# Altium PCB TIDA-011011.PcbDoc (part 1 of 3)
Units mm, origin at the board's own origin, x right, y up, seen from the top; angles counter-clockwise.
Board outline 61 x 47.5 mm, 4 copper layers (Top Layer, Layer 1, Layer 2, Bottom Layer), stack 1.787 mm thick; 171 components, 73 nets, 455 pads, 298 vias.
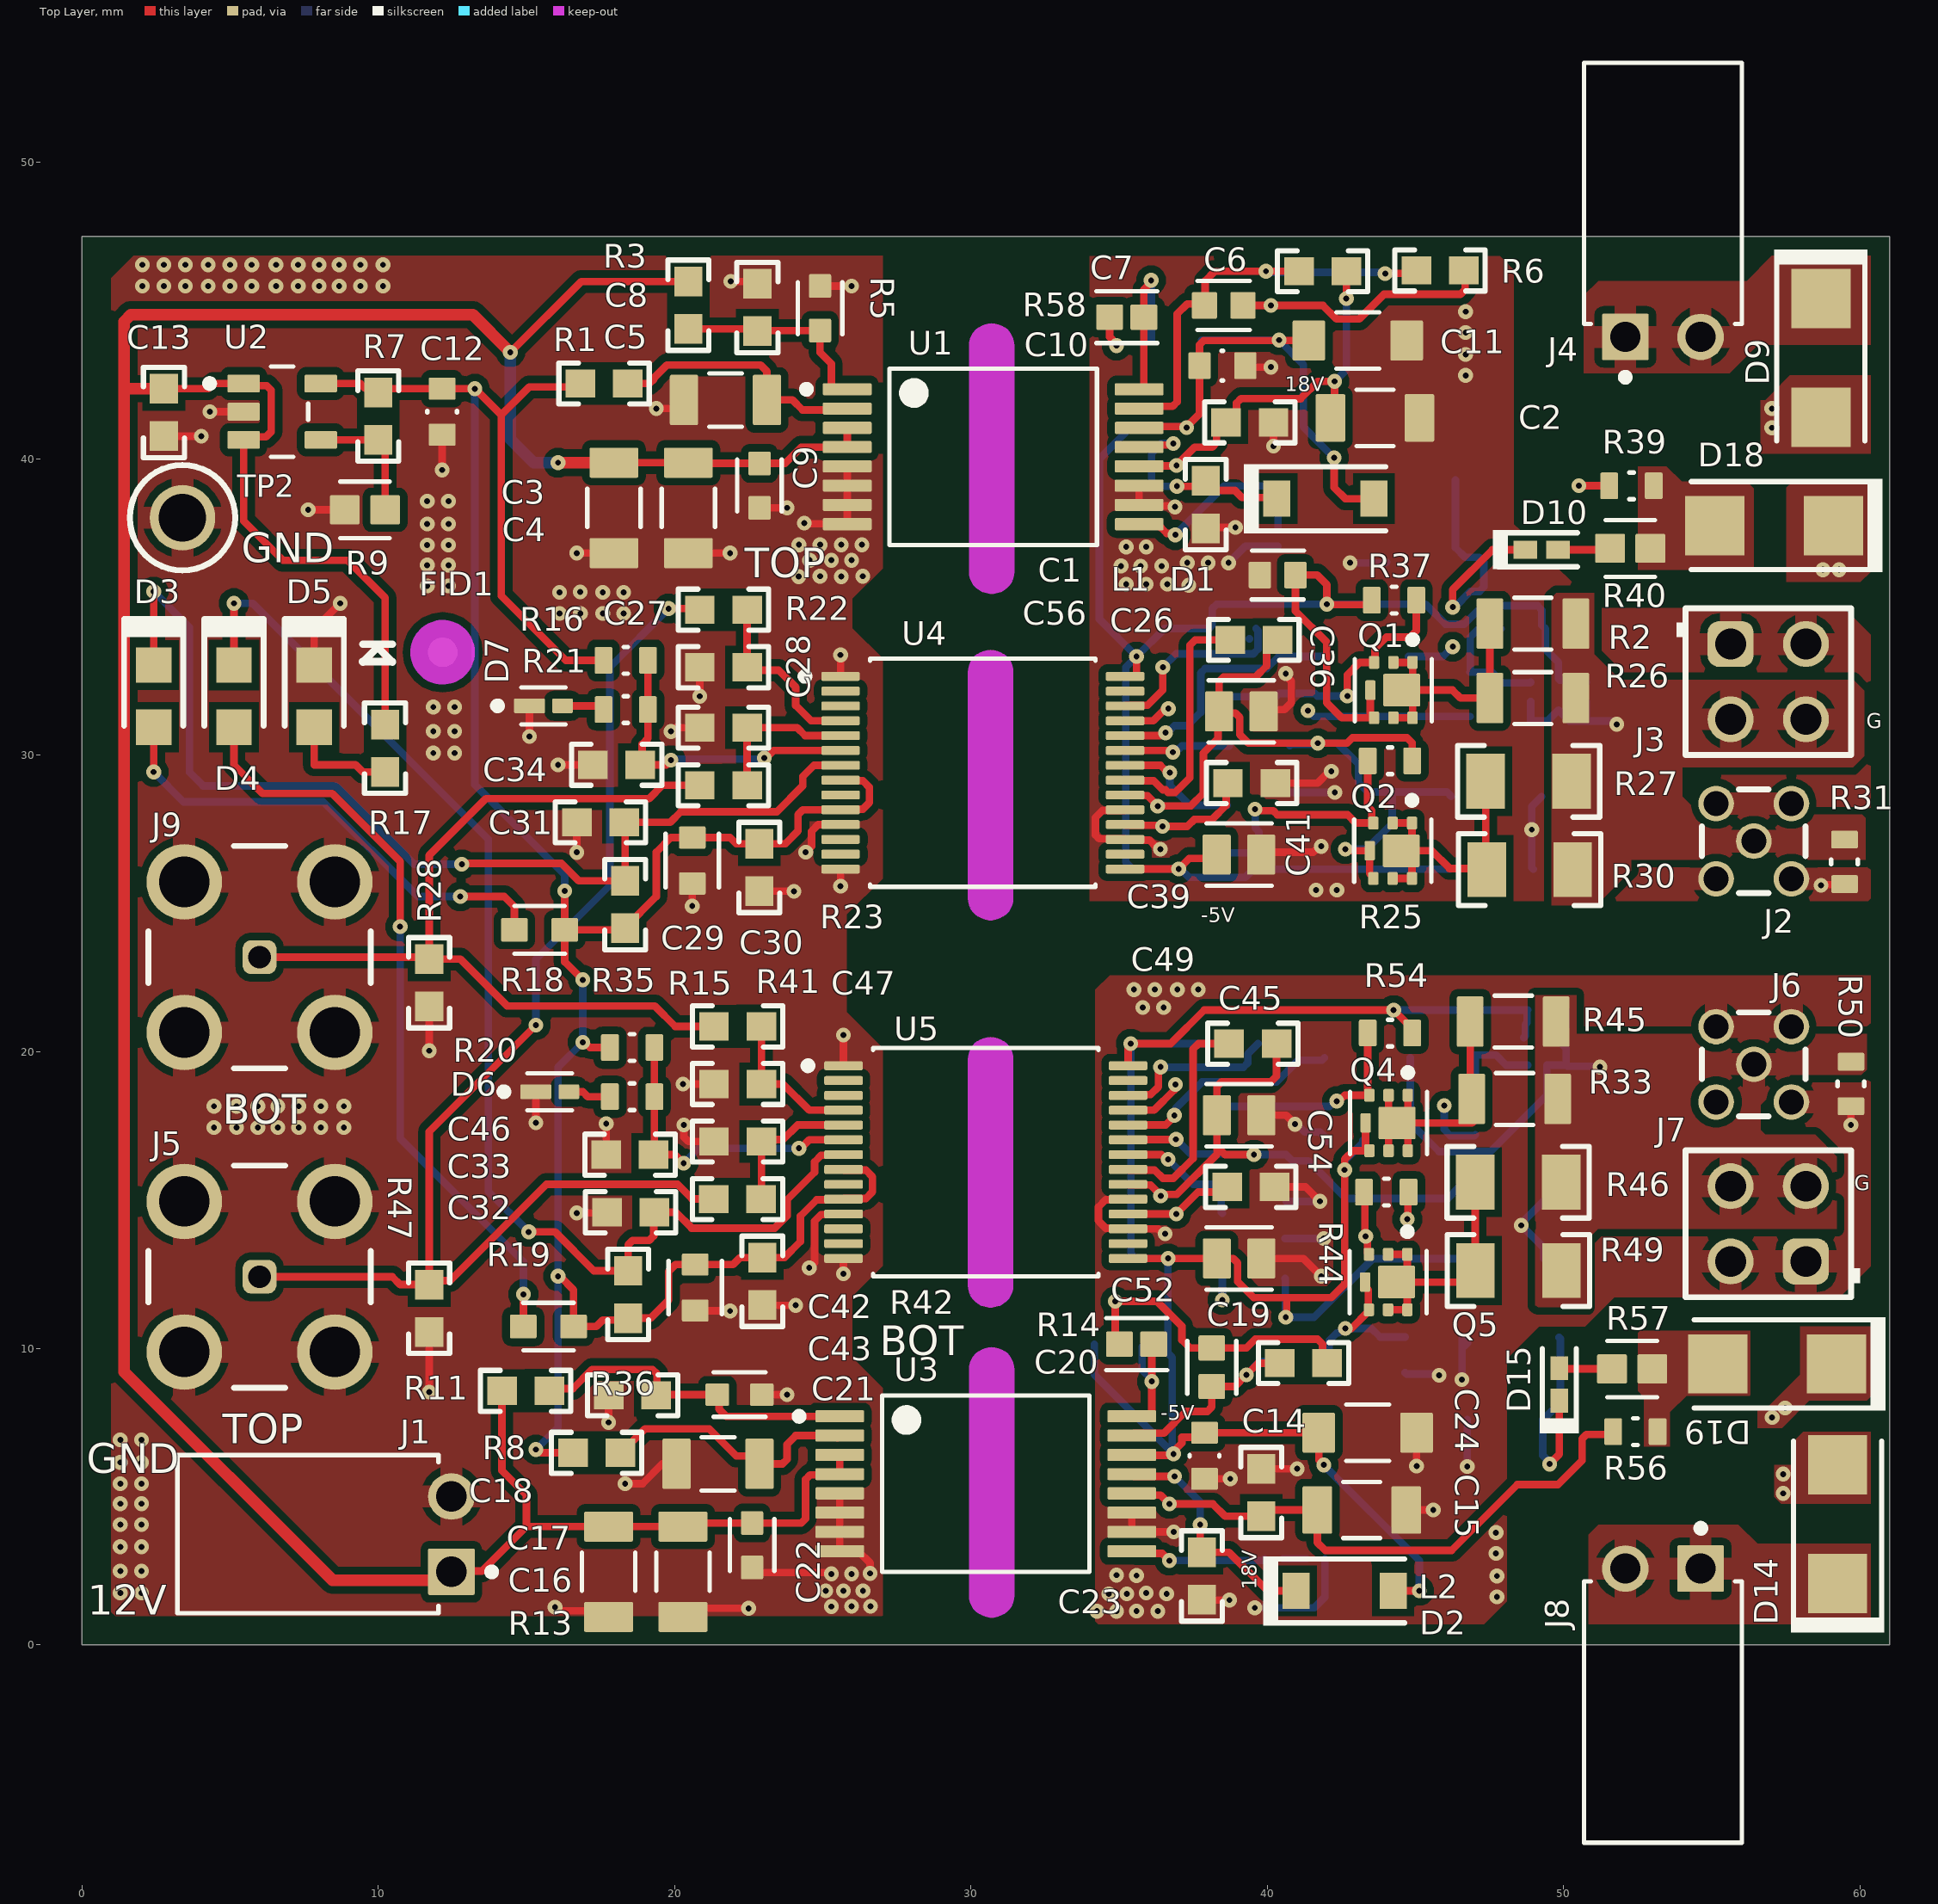
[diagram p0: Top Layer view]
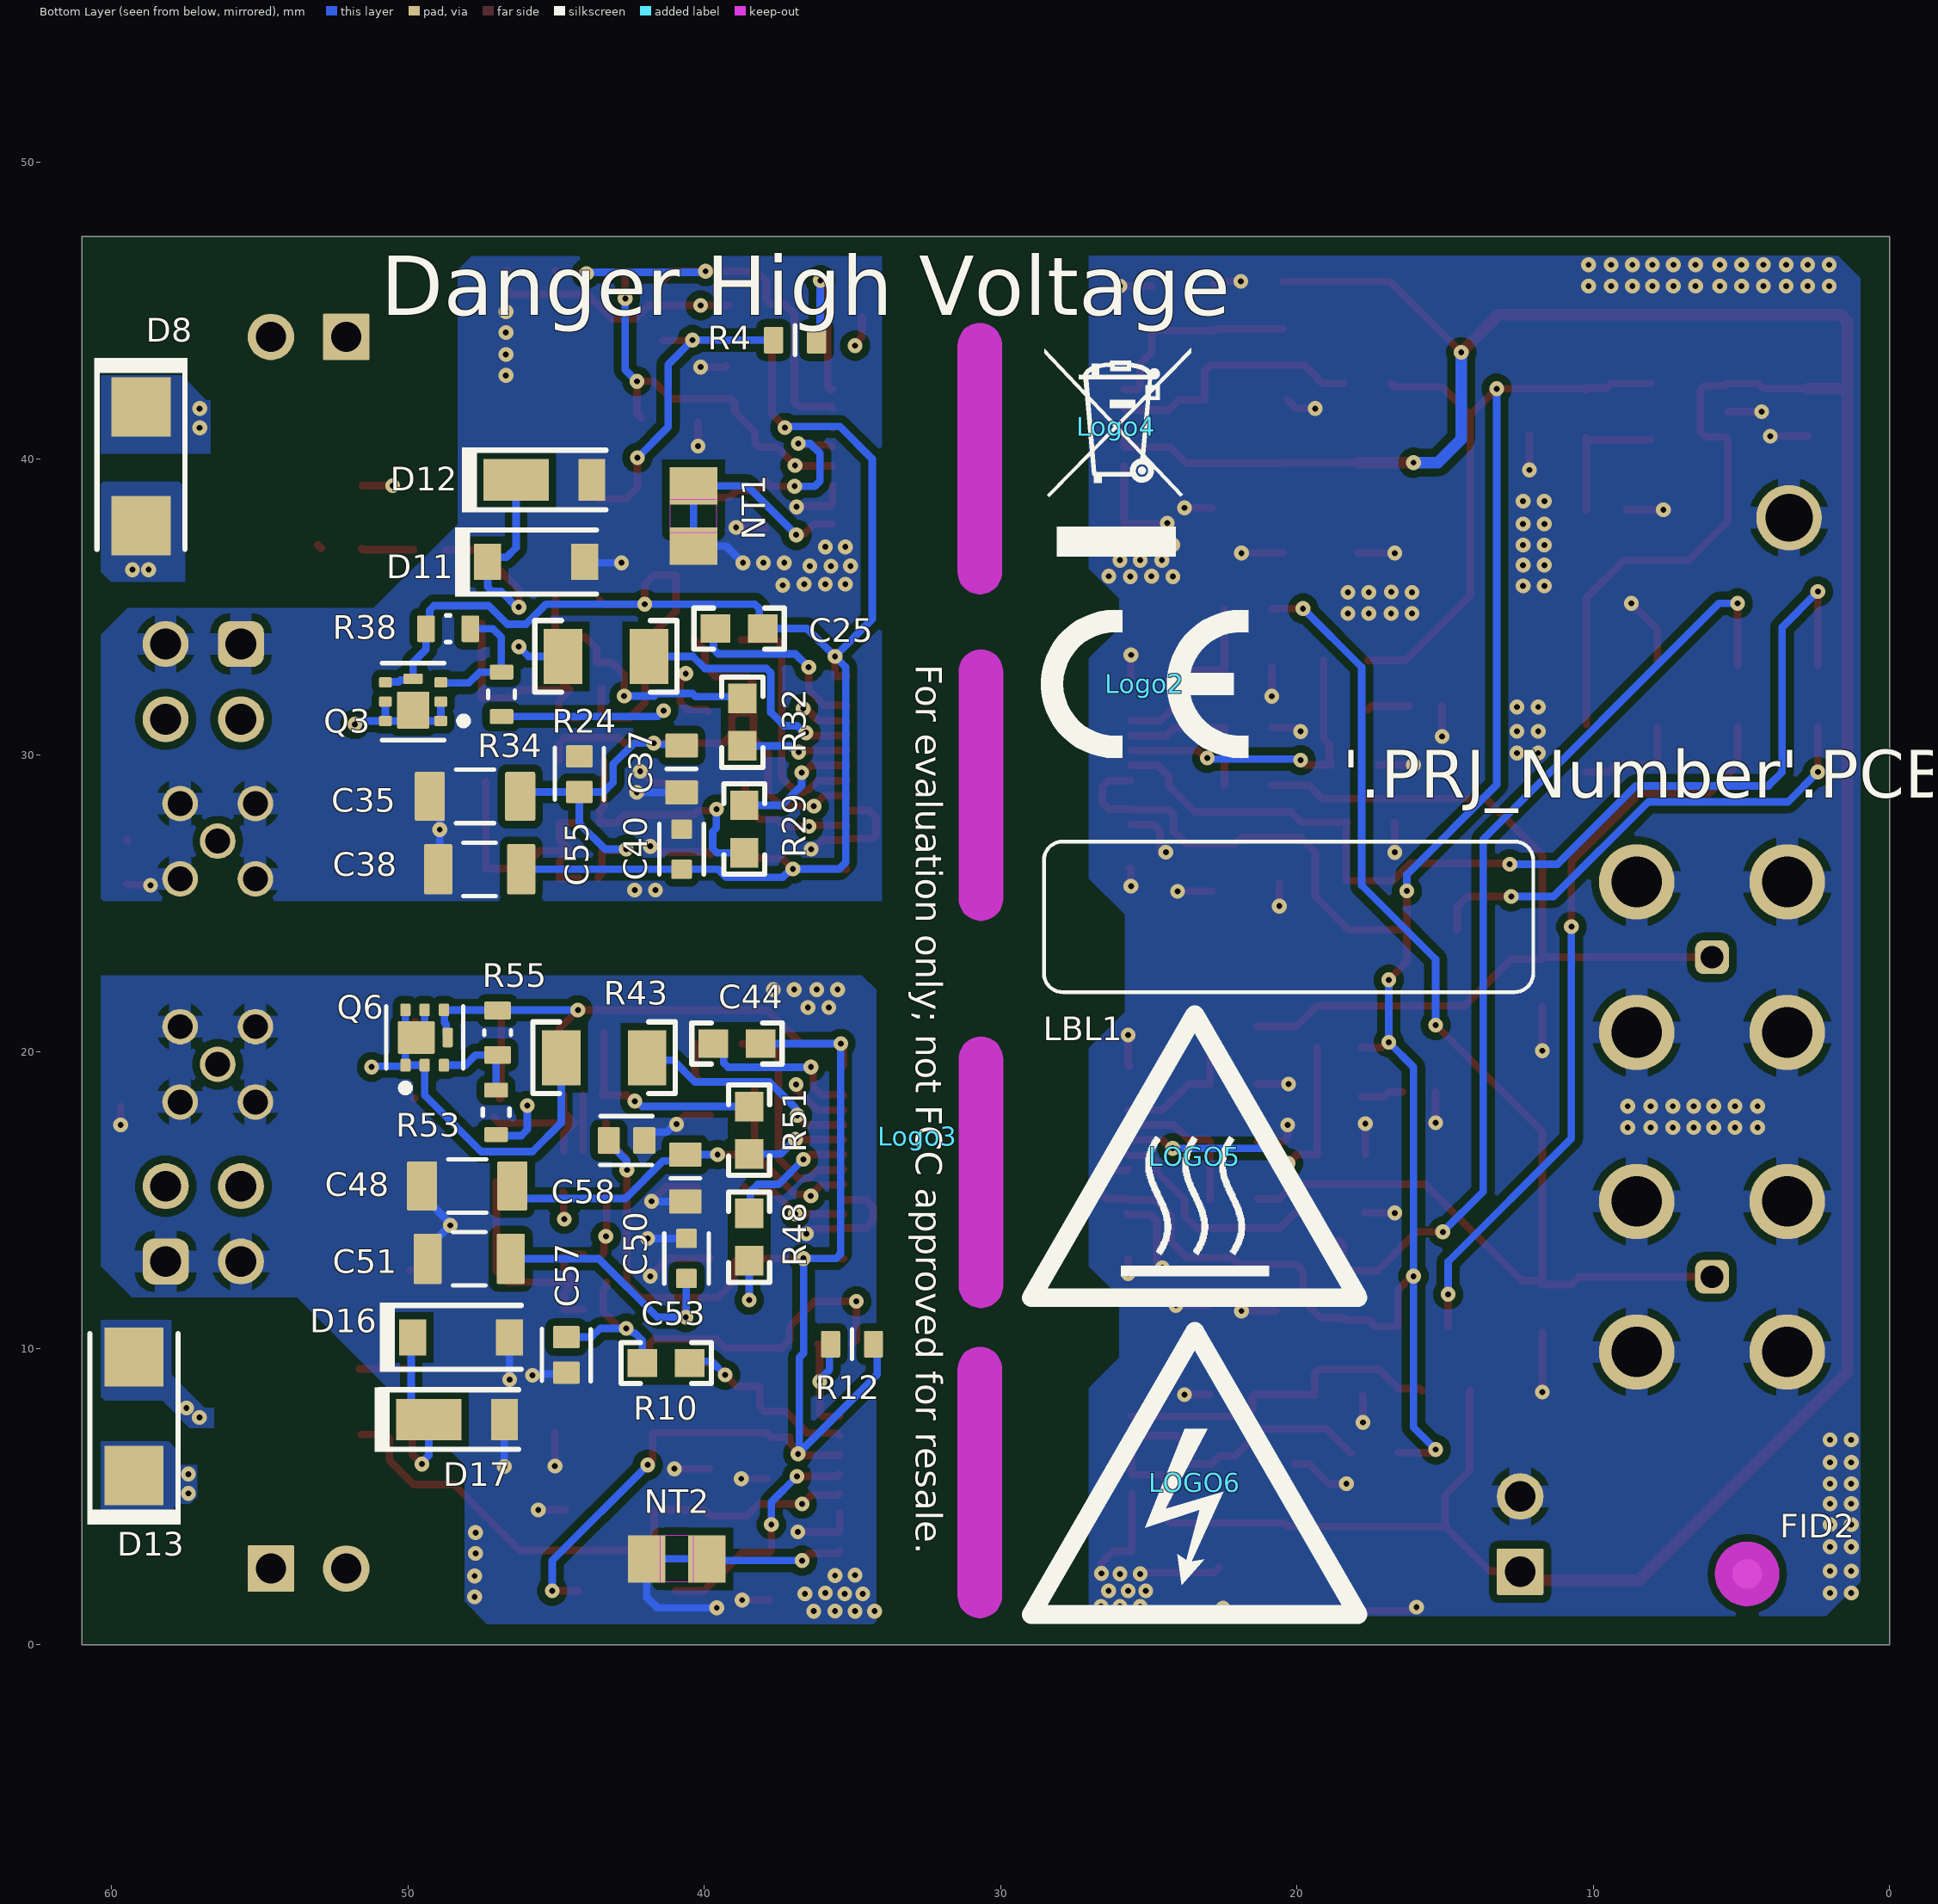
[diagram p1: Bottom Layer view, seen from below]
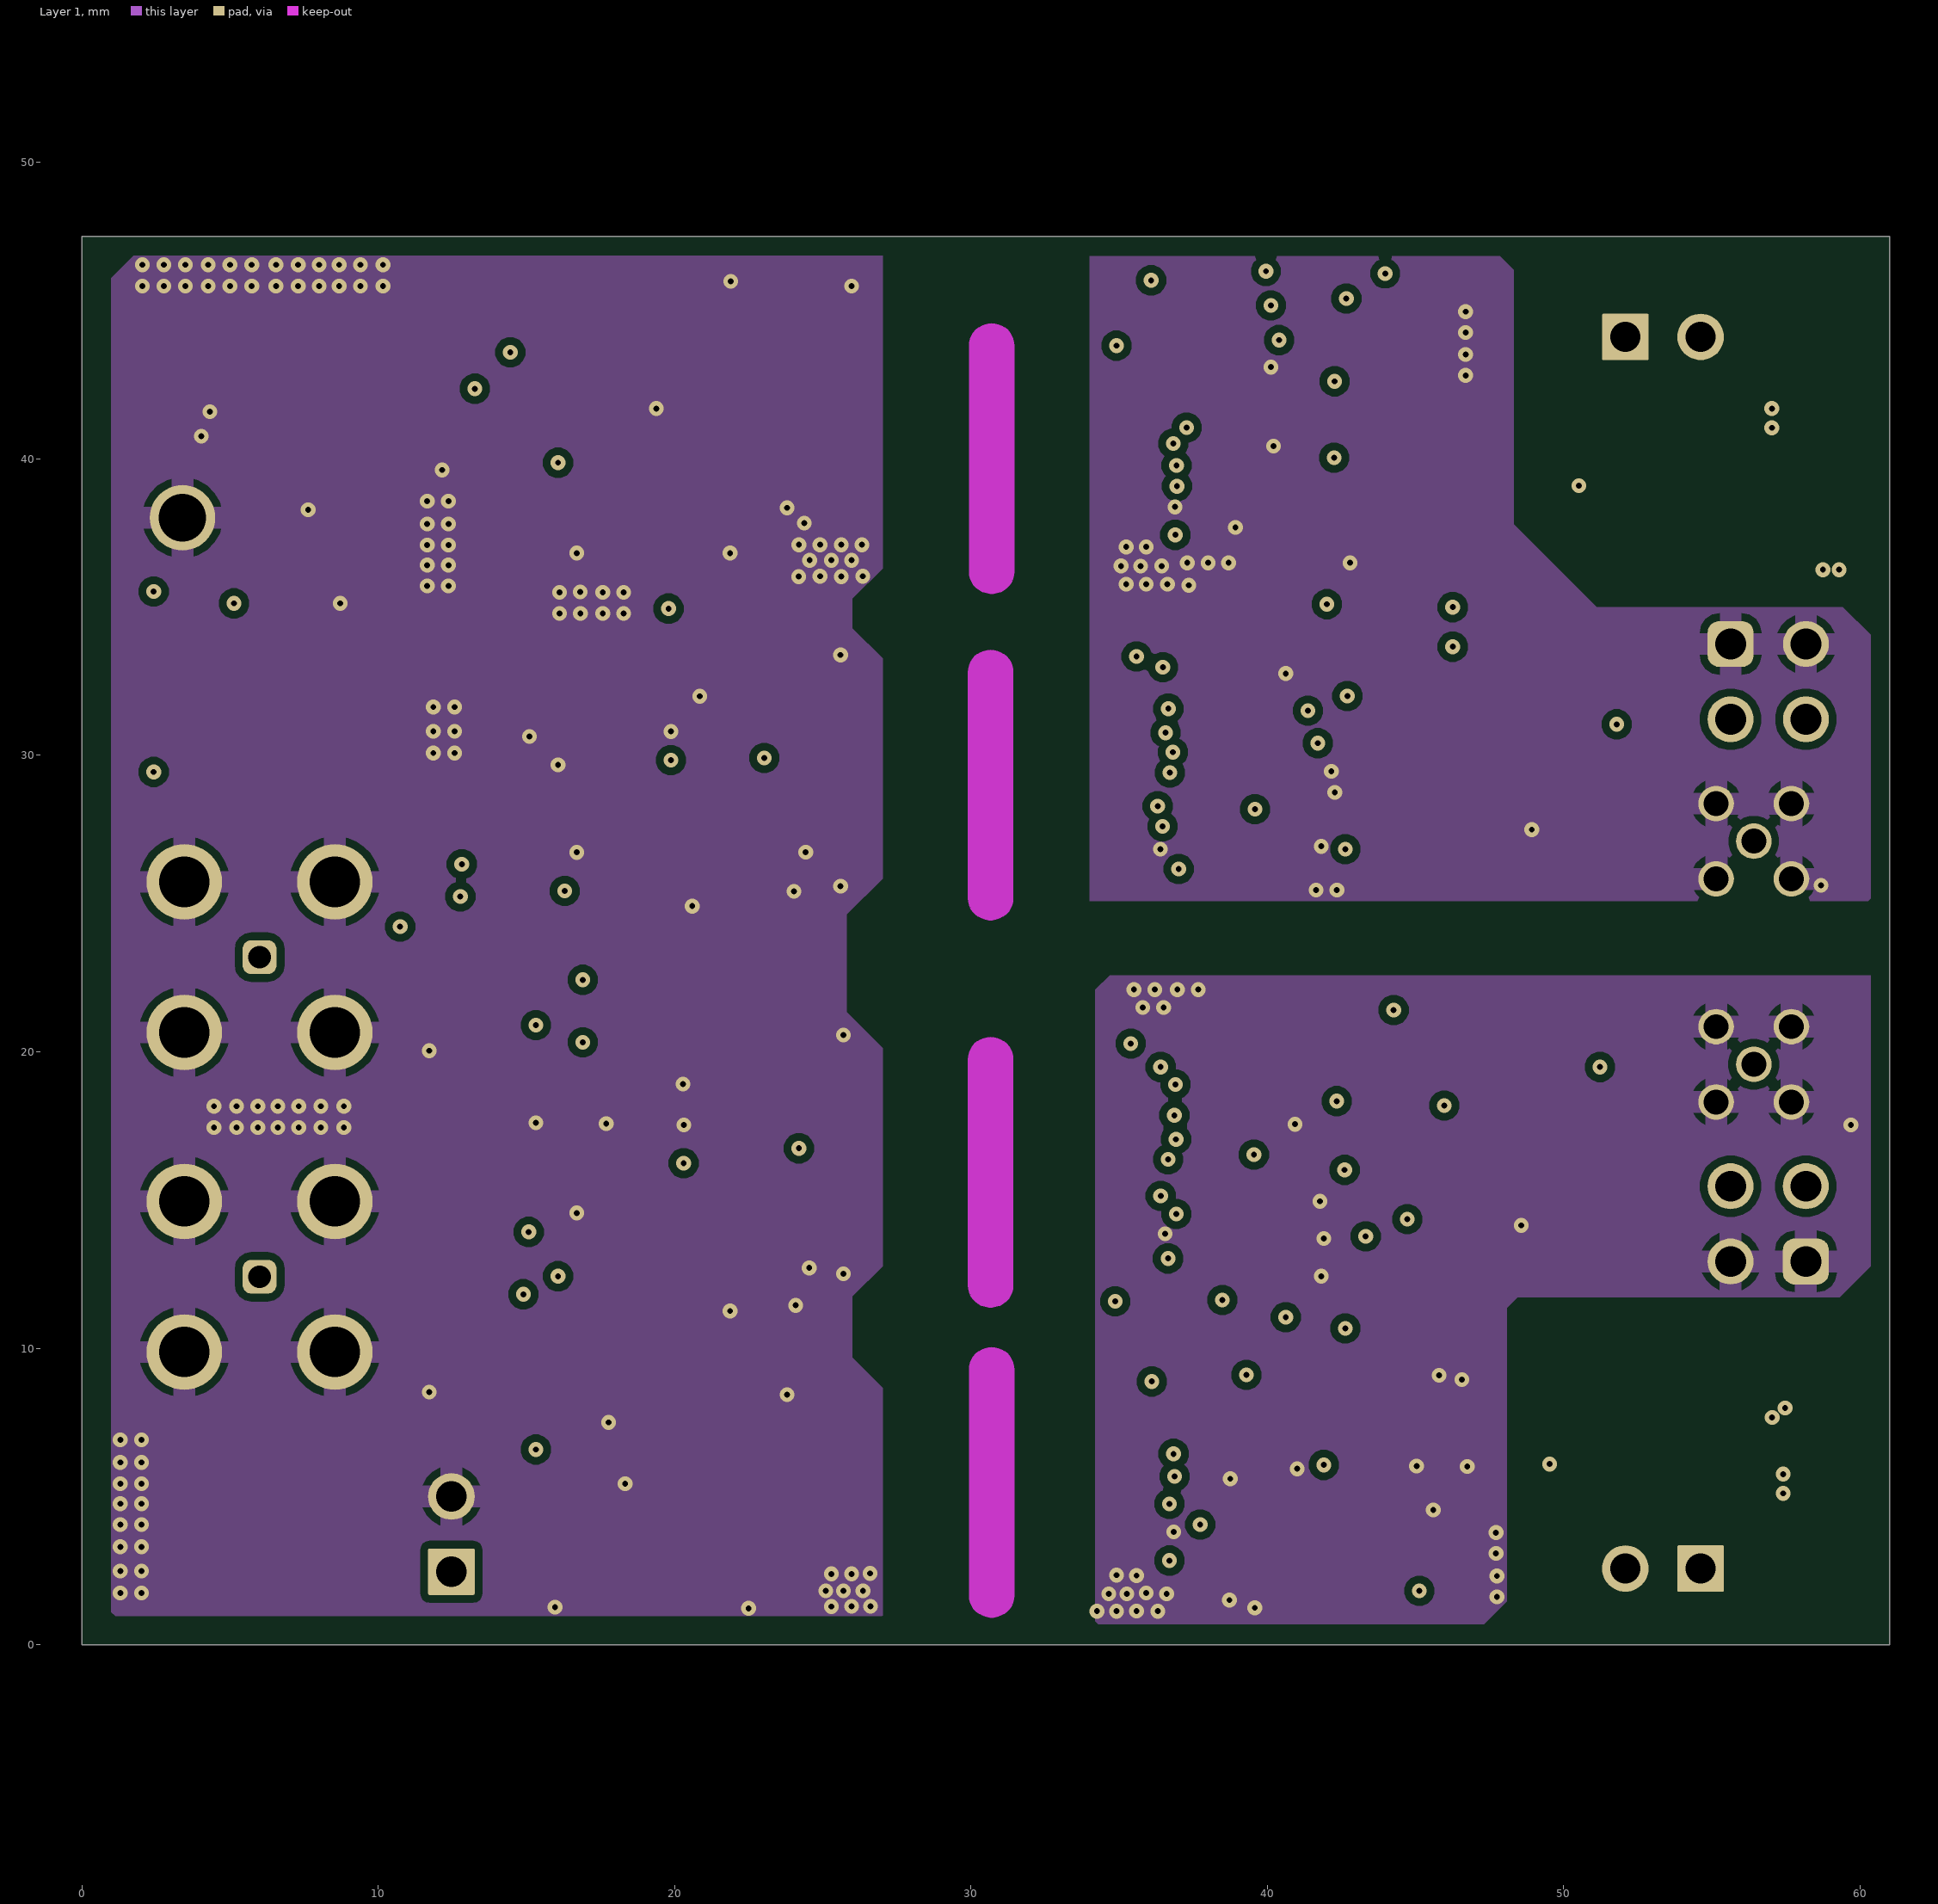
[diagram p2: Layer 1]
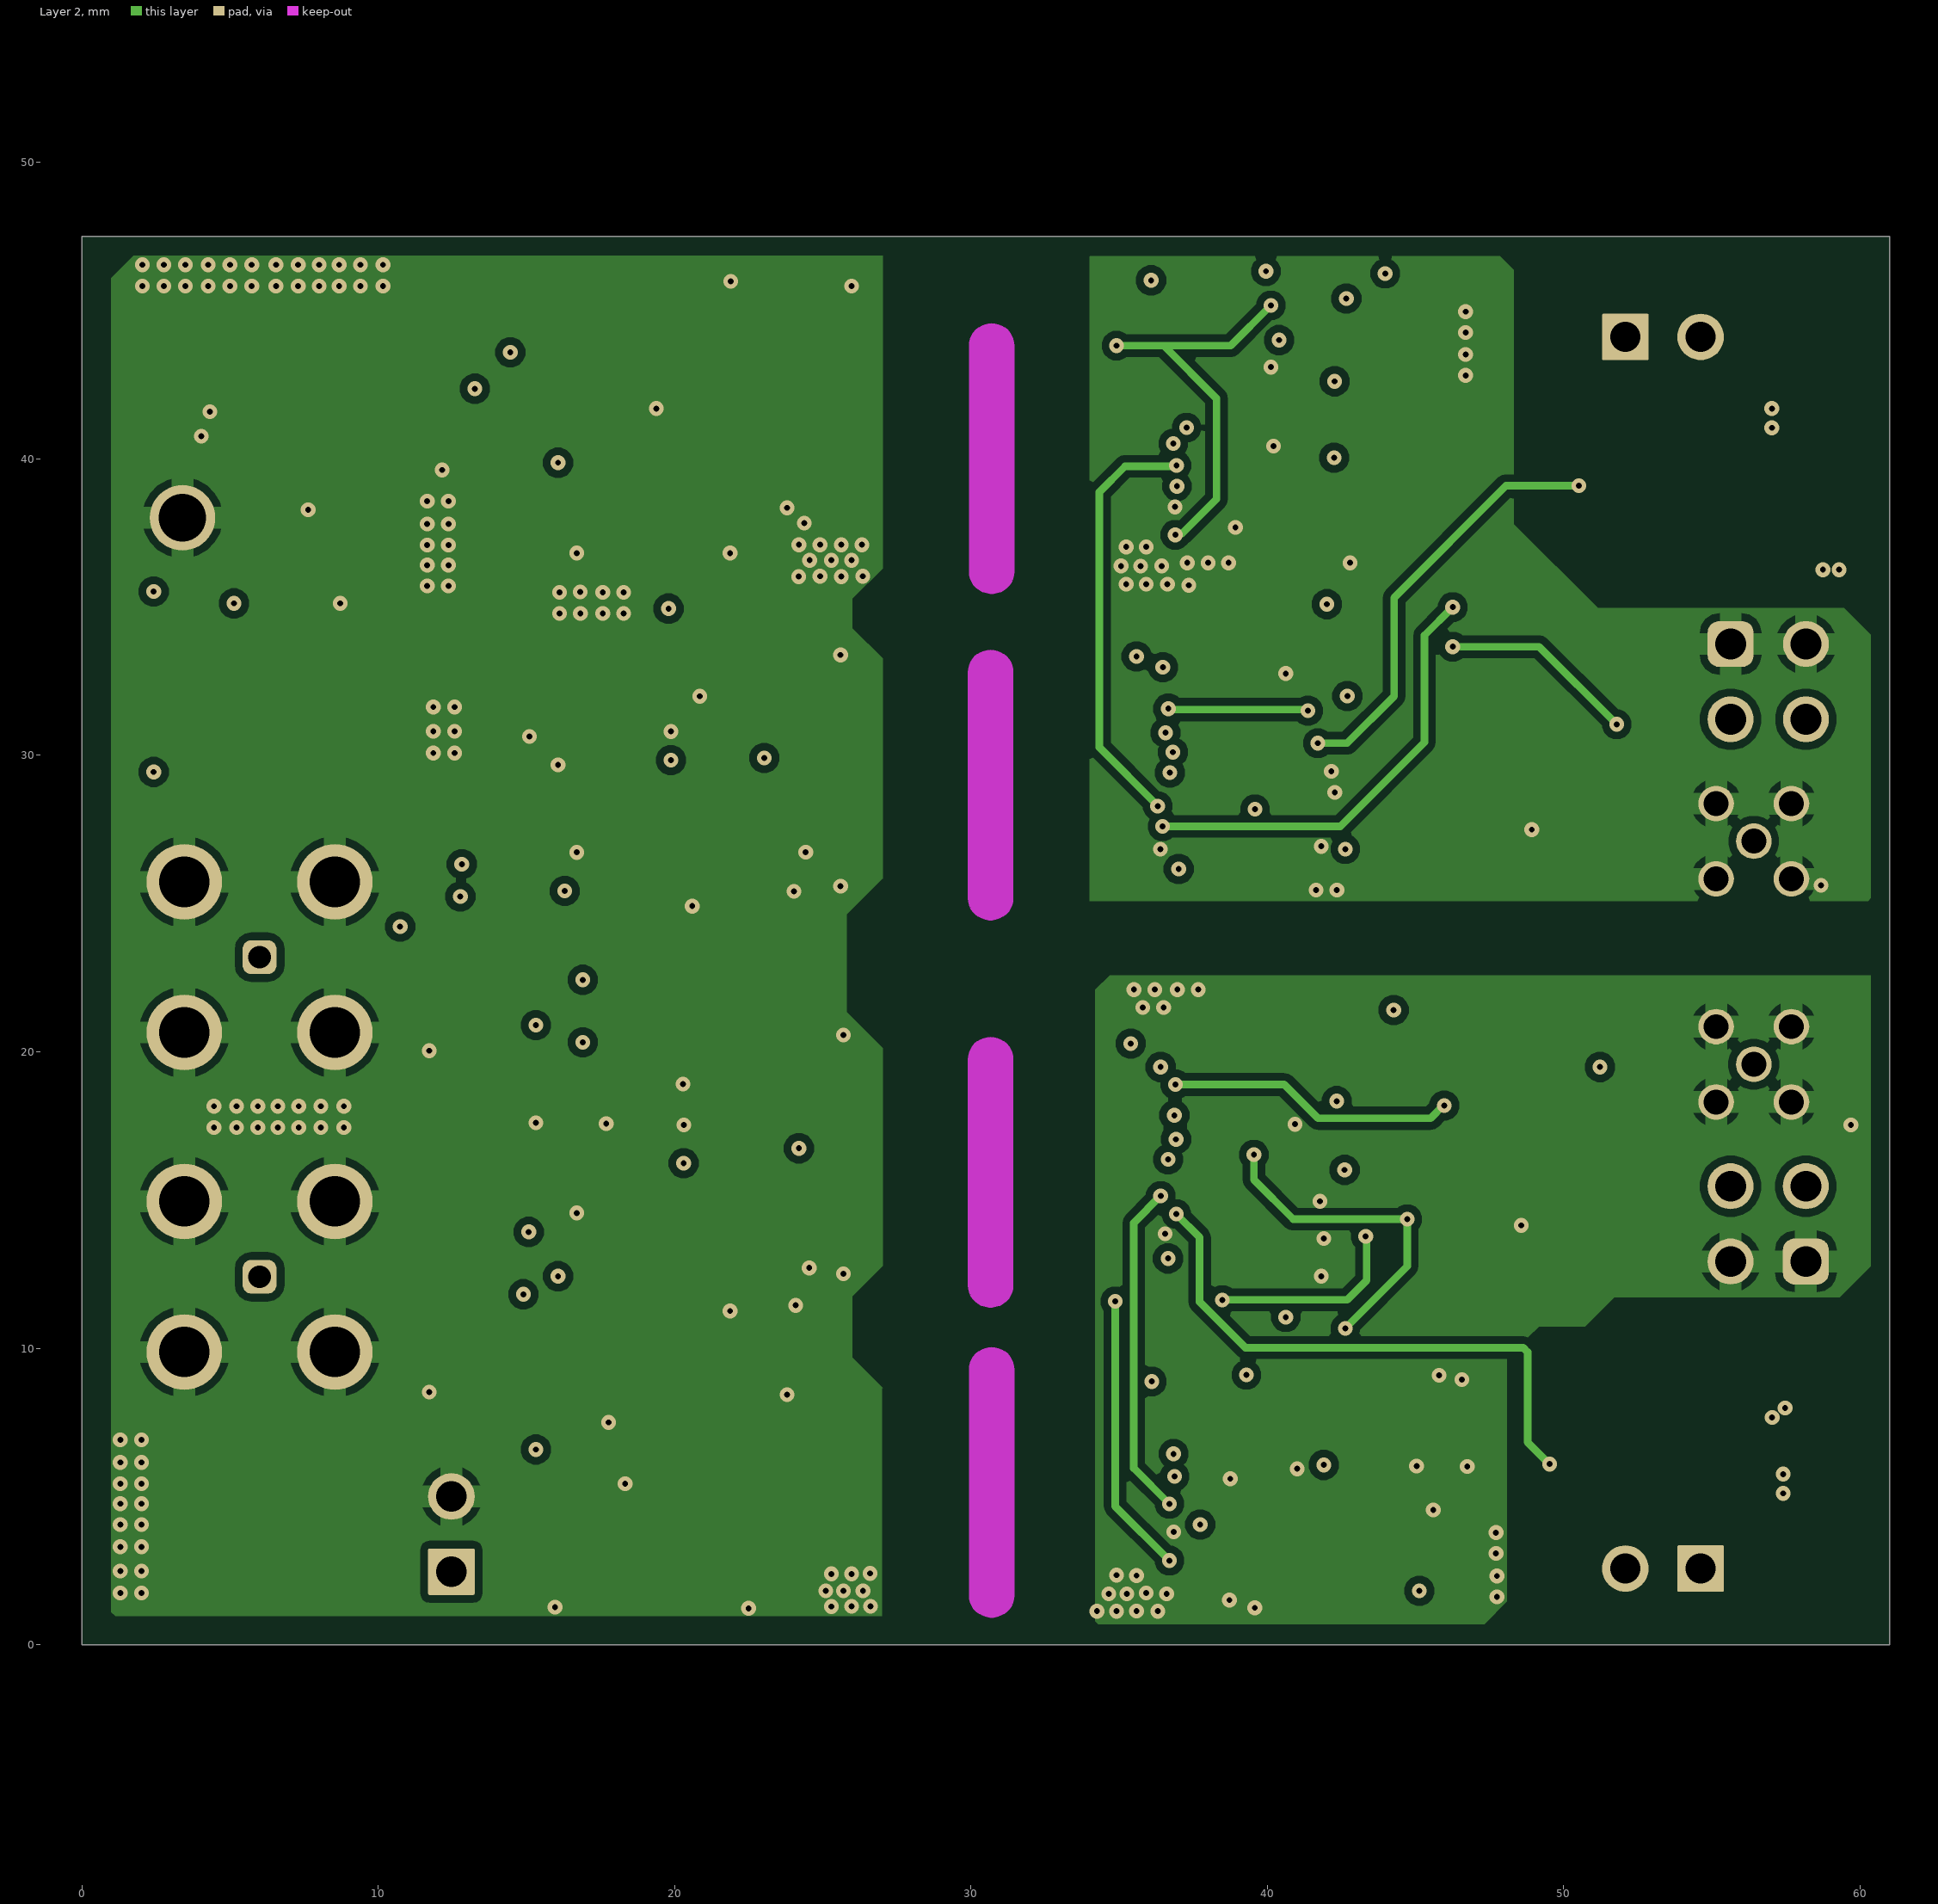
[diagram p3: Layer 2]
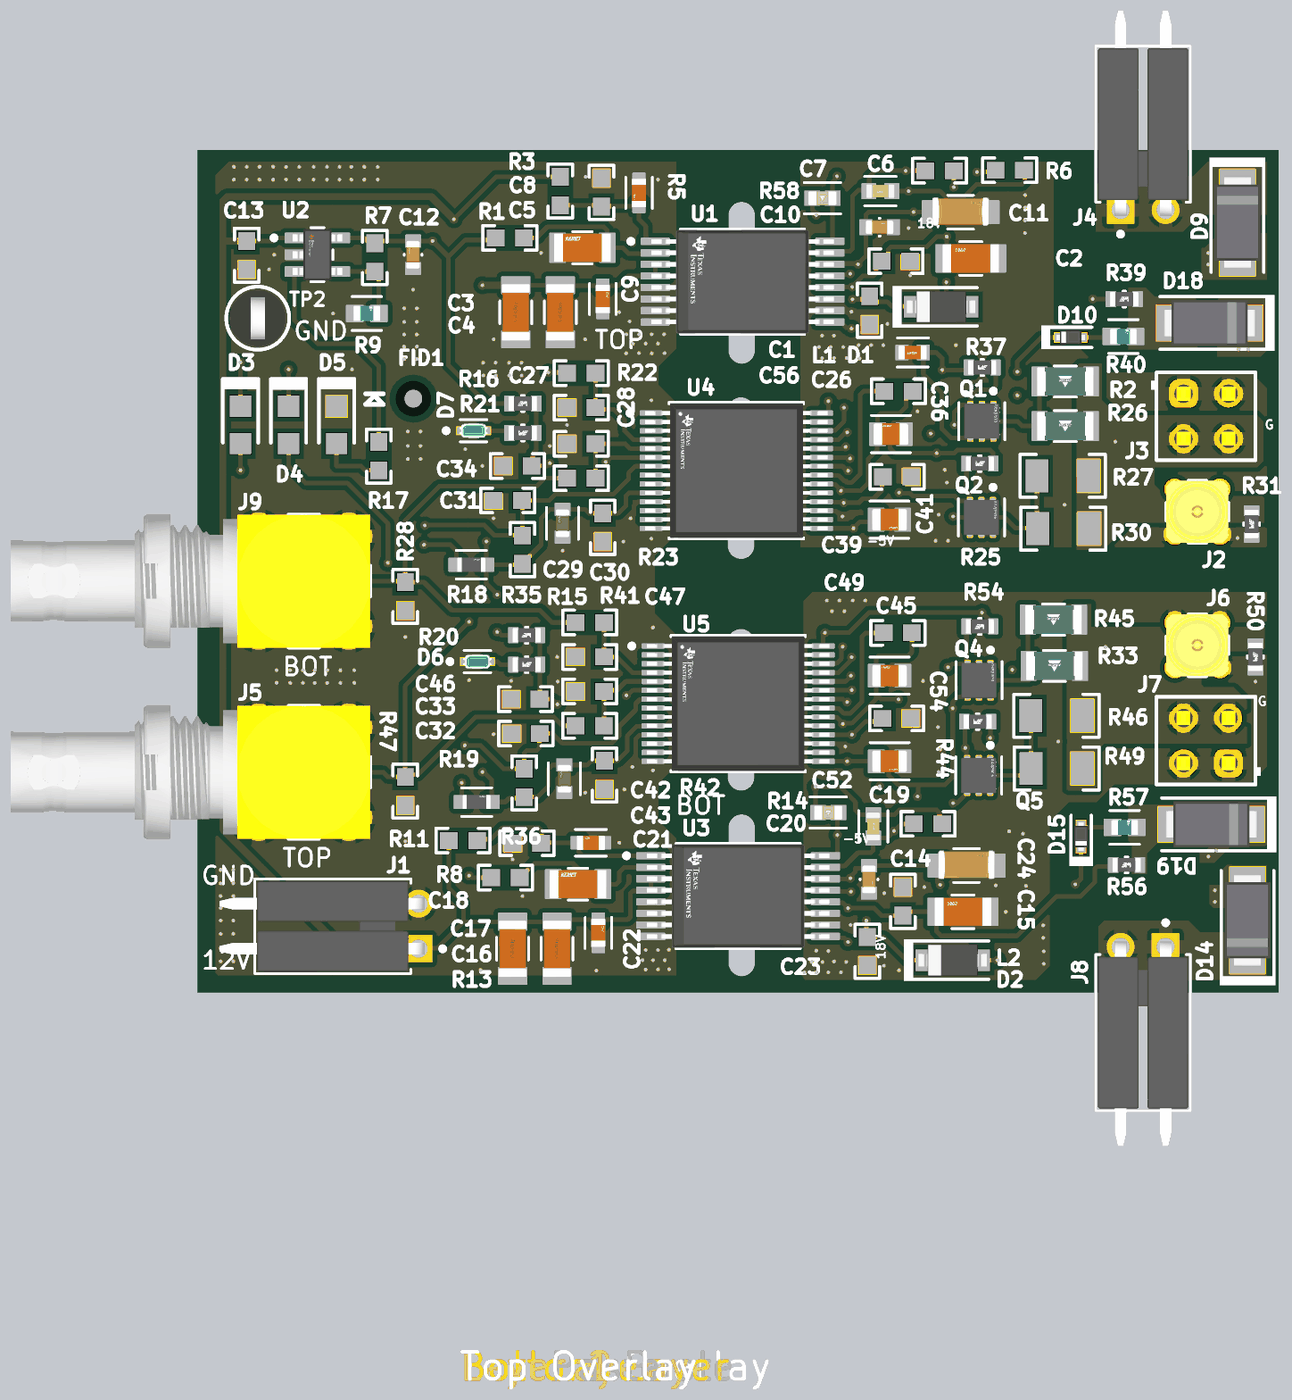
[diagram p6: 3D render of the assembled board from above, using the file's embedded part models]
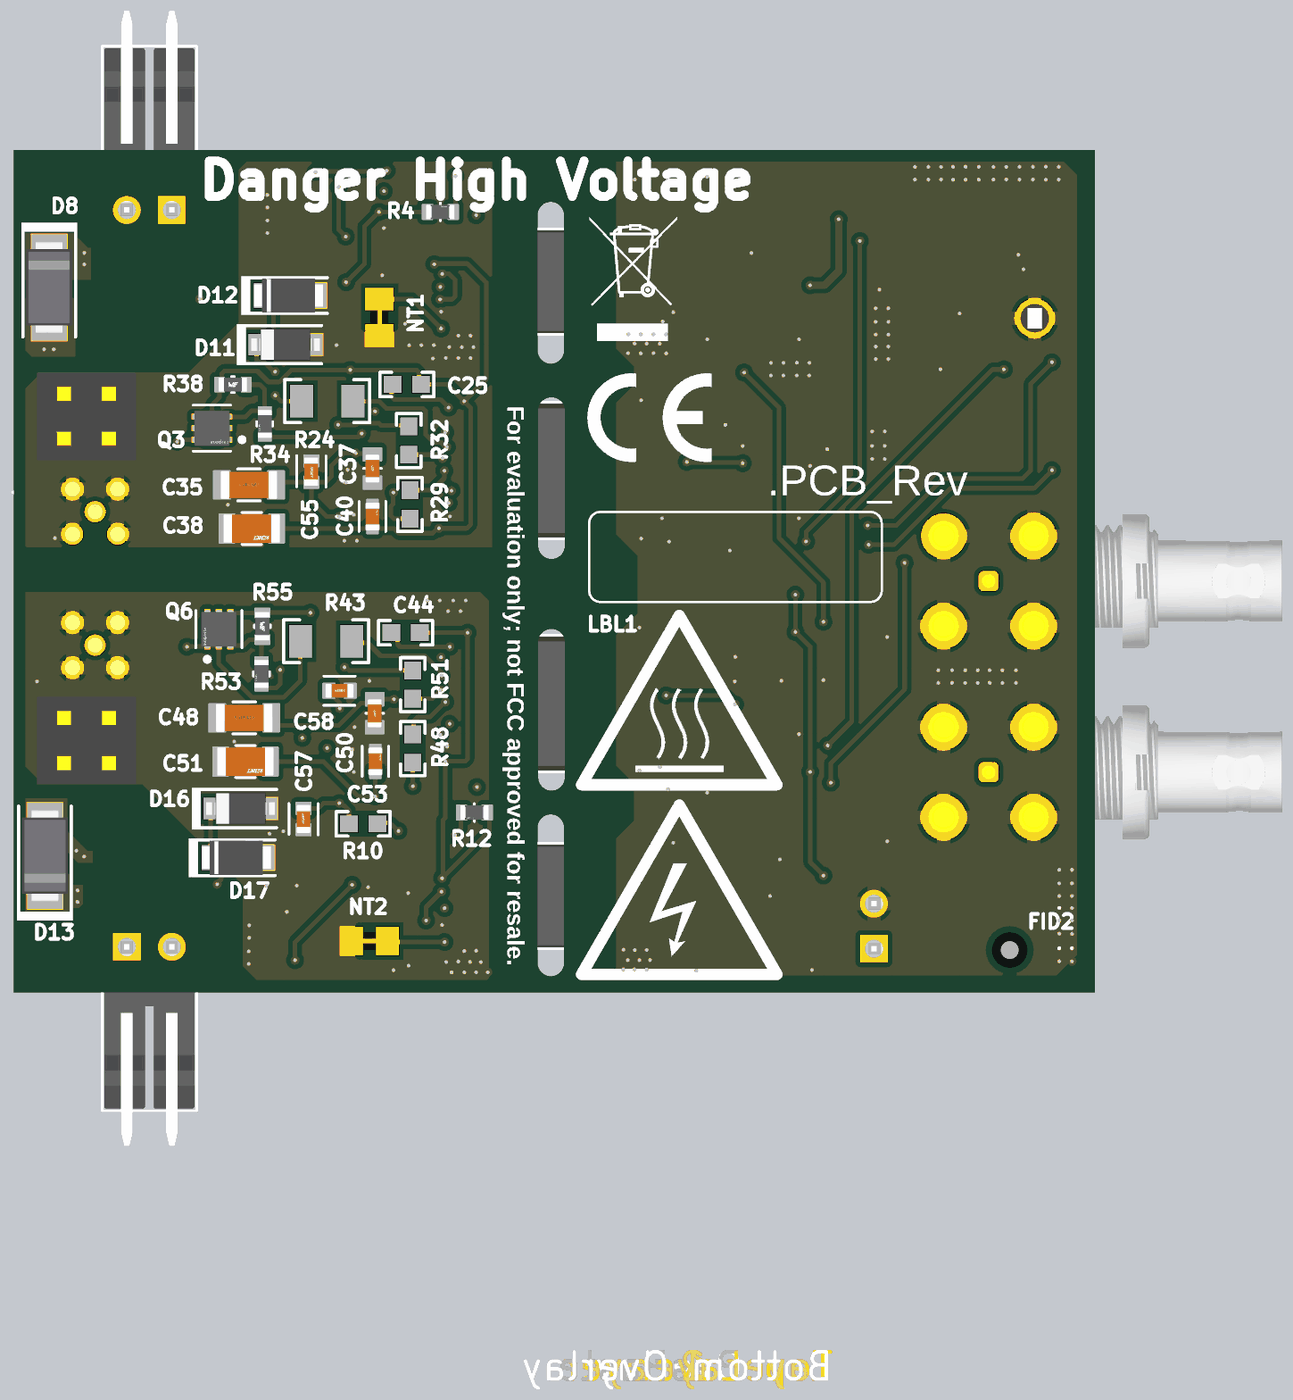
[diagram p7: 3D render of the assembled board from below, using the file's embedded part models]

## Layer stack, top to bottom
Top Solder: solder mask 0.0102, Solder Resist, Dk 3.5
Top Layer: signal copper 0.0356
Dielectric 1: core 0.0711, PP-006, Dk 4.1
Layer 1: signal copper 0.035
Dielectric1: core 1.5037, FR-4 High Tg, Dk 4.8
Layer 2: signal copper 0.035
Dielectric 2: core 0.0711, PP-006, Dk 4.1
Bottom Layer: signal copper 0.0356
Bottom Solder: solder mask 0.0102, Solder Resist, Dk 3.5

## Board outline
0,0 61,0 61,47.5 0,47.5
cut-out: 31.45,1.666 cw(c30.7,1.666) 29.95,1.666 29.95,9.286 cw(c30.7,9.286) 30.7,10.036 cw(c30.7,9.286) 31.45,9.286
cut-out: 31.413,12.127 cw(c30.663,12.127) 29.913,12.127 29.913,19.747 cw(c30.663,19.747) 30.663,20.498 cw(c30.663,19.747) 31.413,19.747
cut-out: 31.413,25.188 cw(c30.663,25.188) 29.913,25.188 29.913,32.808 cw(c30.663,32.808) 30.663,33.558 cw(c30.663,32.808) 31.413,32.808
cut-out: 31.45,36.2 cw(c30.7,36.2) 29.95,36.2 29.95,43.82 cw(c30.7,43.82) 30.7,44.57 cw(c30.7,43.82) 31.45,43.82

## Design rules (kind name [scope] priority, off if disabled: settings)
AcuteAngle [All] p1: minimum=4.50000000000000E+0001 checktracksonly=FALSE
AssemblyTestPointUsage [All] p1: valid=2
BoardOutlineClearance BoardOutlineClearance_MountingHoles [OnCopper and InComponentClass('Mounting Holes')] p1: gap=1 ignorepadtopadclearanceinfootprint=FALSE
BoardOutlineClearance BoardOutlineClearance_Poly [OnCopper and IsPoly] p2: gap=0.635 ignorepadtopadclearanceinfootprint=FALSE
BoardOutlineClearance [OnCopper and Not InComponentClass('Logo') and not InComponentClass('FiducialMark') and not InRegion(1000,500,4000,800) and not InPoly] p3: gap=0.4 ignorepadtopadclearanceinfootprint=FALSE
Clearance Clearance_Keepouts [((IsTrack Or IsArc) And Not InPoly) And IsFree and IsKeepOut vs ((IsTrack Or IsArc) And Not InPoly) And IsFree and IsKeepOut] p1: gap=0 ignorepadtopadclearanceinfootprint=FALSE
Clearance Clearance_Poly [InPolygon] p2: gap=0.254 ignorepadtopadclearanceinfootprint=TRUE
Clearance Clearance_FiducialMark [IsKeepOut and InComponentClass('FiducialMark') vs IsPad and InComponentClass('FiducialMark')] p3: gap=0 ignorepadtopadclearanceinfootprint=FALSE
Clearance [All] p4: gap=0.2 ignorepadtopadclearanceinfootprint=TRUE
ComponentClearance ComponentClearance_MountingHoles_FiducialMarks [InComponentClass('Mounting Holes') vs InComponentClass('FiducialMark')] p1: gap=1.27 collisioncheckmode=3 verticalgap=0.254 showdistances=FALSE
ComponentClearance ComponentClearance_Shunt [InComponentClass('Header') vs InComponentClass('Shunt')] p2: gap=0 collisioncheckmode=3 verticalgap=0 showdistances=FALSE
ComponentClearance ComponentClearance_Logo [InComponentClass('Logo')] p3: gap=0.762 collisioncheckmode=3 verticalgap=0.254 showdistances=FALSE
ComponentClearance ComponentClearance_ScrewToNut [(HasFootprint('NY PMS 440 0025 PH')) vs (HasFootprint('Keystone_1902C'))] p4: gap=0.127 collisioncheckmode=3 verticalgap=0.254 showdistances=FALSE
ComponentClearance ComponentClearance_MountingHoles [InComponentClass('Mounting Holes')] p5: gap=2.54 collisioncheckmode=3 verticalgap=2540 showdistances=FALSE
ComponentClearance ComponentClearance_SmallPassives [HasFootprint('0201*') or HasFootprint('0402*') or HasFootprint('0508') or HasFootprint('0603*') or HasFootprint('0612') or HasFootprint('0805*') or HasFootprint('0815*') or HasFootprint('0830*') or HasFootprint('1206*') or HasFootprint('1210*') or HasFootprint('1808*') or HasFootprint('1812*') or HasFootprint('1825*') or HasFootprint('2010*') or HasFootprint('2220*') or HasFootprint('2225*') or HasFootprint('2512*') or HasFootprint('2728*') or HasFootprint('3518*') vs HasFootprint('0201*') or HasFootprint('0402*') or HasFootprint('0508') or HasFootprint('0603*') or HasFootprint('0612') or HasFootprint('0805*') or HasFootprint('0815*') or HasFootprint('0830*') or HasFootprint('1206*') or HasFootprint('1210*') or HasFootprint('1808*') or HasFootprint('1812*') or HasFootprint('1825*') or HasFootprint('2010*') or HasFootprint('2220*') or HasFootprint('2225*') or HasFootprint('2512*') or HasFootprint('2728*') or HasFootprint('3518*')] p6: gap=0.38 collisioncheckmode=3 verticalgap=0.254 showdistances=FALSE
ComponentClearance ComponentClearance_THtoSMT [IsThruComponent vs IsSMTComponent] p7: gap=0.762 collisioncheckmode=3 verticalgap=0.762 showdistances=FALSE
ComponentClearance ComponentClearance_THtoTH [IsThruComponent vs IsThruComponent] p8: gap=0.508 collisioncheckmode=3 verticalgap=0.762 showdistances=FALSE
ComponentClearance [All] p9: gap=0.508 collisioncheckmode=3 verticalgap=0.254 showdistances=FALSE
DiffPairsRouting [All] p1: maxlimit=2.54 minlimit=0.254 mostfreqgap=0.254 toplayer_minwidth=0.381 toplayer_maxwidth=0.381 toplayer_prefwidth=0.381 midlayer1_minwidth=0.381 midlayer1_maxwidth=0.381 midlayer1_prefwidth=0.381 midlayer2_minwidth=0.381 midlayer2_maxwidth=0.381 midlayer2_prefwidth=0.381 bottomlayer_minwidth=0.381 bottomlayer_maxwidth=0.381 bottomlayer_prefwidth=0.381 maxuncoupledlength=25.4
FabricationTestPointUsage TestPointUsage [All] p1: valid=2 allowmultiple=FALSE
FabricationTestpoint Testpoint [All] p1: side=3 testpointundercomponent=TRUE minsize=1.016 maxsize=2.54 preferedsize=1.524 minholesize=0 maxholesize=1.016 preferedholesize=0.813 testpointgrid=0.025 allowsidetop=TRUE allowsidebottom=TRUE usegrid=TRUE gridtolerance=0
FanoutControl Fanout_LCC [IsLCC] p1: bgadir=Out bgaviamode=Centered fanoutstyle=Auto fanoutdirection=Alternating viagrid=0.025 // Fanout_LCC (Default Rule)
FanoutControl Fanout_BGA [IsBGA] p2: bgadir=Out bgaviamode=Centered fanoutstyle=Auto fanoutdirection=Alternating viagrid=0.025 // Fanout_BGA (Default Rule)
FanoutControl Fanout_Default [All] p4: bgadir=Out bgaviamode=Centered fanoutstyle=Auto fanoutdirection=Alternating viagrid=0.025 // Fanout_Default (Default Rule)
FanoutControl Fanout_Small [(CompPinCount < 5)] p5: bgadir=Out bgaviamode=Centered fanoutstyle=Auto fanoutdirection=OutThenIn viagrid=0.025 // Fanout_Small (Default Rule)
HoleSize [All] p1: absolutevalues=TRUE maxlimit=6.375 minlimit=0.2 maxpercent=80.000 minpercent=20.000
MinimumAnnularRing MinimumAnnularRing_ThermalPadVias [IsVia and InAnyComponent] p1: minimumring=0.15
MinimumAnnularRing [All] p2: minimumring=0.15
MinimumSolderMaskSliver MinimumSolderMaskSliver_Logo [InComponentClass('Logo') vs InComponentClass('Logo')] p1: minsoldermaskwidth=0.018
MinimumSolderMaskSliver [All] p2: minsoldermaskwidth=0.1
PlaneConnect [All] p1: planeconnectstyle=Relief reliefexpansion=0.254 reliefentries=4 reliefconductorwidth=0.254 reliefairgap=0.254
PolygonConnect [All] p1: thpad.connectstyle=Relief thpad.reliefconductorwidth=0.75 thpad.reliefentries=4 thpad.polygonreliefangle="90 Angle" thpad.airgapwidth=0.25 smdpad.connectstyle=Direct smdpad.reliefconductorwidth=0.254 smdpad.reliefentries=4 smdpad.polygonreliefangle="90 Angle" smdpad.airgapwidth=0.254 via.connectstyle=Direct via.reliefconductorwidth=0.254 via.reliefentries=4 via.polygonreliefangle="90 Angle" via.airgapwidth=0.254
RoutingVias ThermalPadVias [IsVia and InAnyComponent] p1: holewidth=0.2 width=0.5 viastyle="Through Hole" minholewidth=0.2 minwidth=0.5 maxholewidth=0.33 maxwidth=0.6
RoutingVias [All] p2: holewidth=0.406 width=0.864 viastyle="Through Hole" minholewidth=0.2 minwidth=0.61 maxholewidth=1.016 maxwidth=1.651
SilkToBoardRegionClearance [Not ((IsComment or IsDesignator) And (Hide <> 'False')) and not InRegion(1000,500,4000,800)] p1:
SilkToSilkClearance SilkToSilkClearance_Pb-FreeLogo [(HasFootprint('Pb-Free_Overlay_Medium') OR HasFootprint('Pb-Free_Overlay_Small')) vs (HasFootprint('Pb-Free_Overlay_Medium') OR HasFootprint('Pb-Free_Overlay_Small'))] p1: silktosilkclearance=0
SilkToSilkClearance [All] p2: silktosilkclearance=0.1
SilkToSolderMaskClearance SilkToComponentPadClearance [(IsPad or IsFill or IsRegion) and InAnycomponent] p1: minsilkscreentomaskgap=0.127 clearancetoexposedcopper=TRUE
SilkToSolderMaskClearance "Silk to Solder Mask Opening" [All] p2: minsilkscreentomaskgap=0.1 clearancetoexposedcopper=FALSE
SolderMaskExpansion [All] p1: expansion=0.05 istentingtop=FALSE
UnRoutedNet [All] p1: checkbadconnections=TRUE
Width [All] p1: maxlimit=2.54 minlimit=0.152 preferedwidth=0.254 checkconnectedcopper=TRUE
14 further rules are at their usual default settings.

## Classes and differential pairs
component class TIDA-011011_DCDC_Supplies: 3 C1 C2 C3 C4 C5 C6 C7 C8 C9 C10 C11 C12 C13 C14 C15 C16 C17 C18 C19 C20 C21 C22 C23 C24 D1 D2 J1 L1 L2 NT1 NT2 R1 R3 R4 R5 R6 R7 R8 R9 R10 R11 R12 R13 R14 R58 TP2 U1 U2 U3
component class TIDA-011011_Hardware: 222 !PCB FID1 FID2 LBL1 Logo2 Logo3 Logo4 LOGO5 LOGO6 ZZ1 ZZ2 ZZ3 ZZ4
component class TIDA-011011_Gate_Drivers: C25 C26 C27 C28 C29 C30 C31 C32 C33 C34 C35 C36 C37 C38 C39 C40 C41 C42 C43 C44 C45 C46 C47 C48 C49 C50 C51 C52 C53 C54 C55 C56 C57 C58 D3 D4 D5 D6 D7 D8 D9 D10 D11 D12 D13 D14 D15 D16 D17 D18 D19 J2 J3 J4 J5 J6 J7 J8 J9 Q1 Q2 Q3 Q4 Q5 Q6 R2 R15 R16 R17 R18 R19 R20 R21 R22 R23 R24 R25 R26 R27 R28 R29 R30 R31 R32 R33 R34 R35 R36 R37 R38 R39 R40 R41 R42 R43 R44 R45 R46 R47 R48 R49 R50 R51 R53 R54 R55 R56 R57 U4 U5
component class Label: LBL1
component class AssemblyNote: ZZ1 ZZ2 ZZ3 ZZ4
component class FiducialMark: FID1 FID2

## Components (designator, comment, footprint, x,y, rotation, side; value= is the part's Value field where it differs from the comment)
C1 "GCM188R71E104KA57D" 0603 39.408,41.231 r0 top value=0.1uF
C2 "KGM31HR71E106KU" FP-KGM31HR71E106KU_1206-MFG 43.628,41.384 r180 top value=10µF
C3 "GMC31X7R106K50NT" FP-GMC31X7R106K50NT_1206-MFG 20.466,38.349 r90 top value=10µF
C4 "GMC31X7R106K50NT" FP-GMC31X7R106K50NT_1206-MFG 17.957,38.349 r90 top value=10µF
C5 "C1206C105J5RECAUTO" FP-C1206C105J5RECAUTO_1206-MFG 21.717,41.989 r0 top value=1µF
C6 "C0603X471F5GACTU" FP-C0603X471F5GACTU_0603-MFG 38.527,45.179 r180 top value=470pF
C7 "VJ0603D220JLAAJ32" FP-VJ0603D220JLAAJ32_0603-IPC_C 35.258,44.782 r0 top value=22pF
C8 "KGM15BR71H104JT" FP-KGM15BR71H104JT_0603-MFG 24.909,45.082 r270 top value=100nF
C9 "KGM15BR71H104JT" FP-KGM15BR71H104JT_0603-MFG 22.867,39.099 r90 top value=100nF
C10 "GRT188C71E225KE13D" FP-GRT188C71E225KE13D_0603-MFG 38.484,43.146 r0 top value=2.2µF
C11 "CGA5L2X7R1E225K160AA" FP-CGA5L2X7R1E225K160AA_1206-MFG 43.051,43.992 r0 top value=2.2µF
C12 "GRT188C71E225KE13D" FP-GRT188C71E225KE13D_0603-MFG 12.16,41.593 r90 top value=2.2µF
C13 "UMK107AB7105KA-T" 0603 2.774,41.568 r270 top value=1uF
C14 "GCM188R71E104KA57D" 0603 39.797,5.136 r90 top value=0.1uF
C15 "KGM31HR71E106KU" FP-KGM31HR71E106KU_1206-MFG 43.185,4.546 r180 top value=10µF
C16 "GMC31X7R106K50NT" FP-GMC31X7R106K50NT_1206-MFG 20.283,2.464 r90 top value=10µF
C17 "GMC31X7R106K50NT" FP-GMC31X7R106K50NT_1206-MFG 17.775,2.464 r90 top value=10µF
C18 "C1206C105J5RECAUTO" FP-C1206C105J5RECAUTO_1206-MFG 21.467,6.104 r0 top value=1µF
C19 "C0603X471F5GACTU" FP-C0603X471F5GACTU_0603-MFG 38.125,9.36 r270 top value=470pF
C20 "VJ0603D220JLAAJ32" FP-VJ0603D220JLAAJ32_0603-IPC_C 35.587,10.14 r0 top value=22pF
C21 "KGM15BR71H104JT" FP-KGM15BR71H104JT_0603-MFG 22.192,8.437 r180 top value=100nF
C22 "KGM15BR71H104JT" FP-KGM15BR71H104JT_0603-MFG 22.617,3.359 r90 top value=100nF
C23 "GRT188C71E225KE13D" FP-GRT188C71E225KE13D_0603-MFG 37.882,6.376 r270 top value=2.2µF
C24 "CGA5L2X7R1E225K160AA" FP-CGA5L2X7R1E225K160AA_1206-MFG 43.385,7.154 r0 top value=2.2µF
C25 "GRT188R61H225KE13D" 0603 38.823,34.277 r0 bottom value=2.2uF
C26 "GRT188R61H225KE13D" 0603 39.546,33.896 r180 top value=2.2uF
C27 "GRM1885C1H201JA01D" 0603 21.65,30.933 r180 top value=200pF
C28 "GRM1885C1H201JA01D" 0603 21.65,32.975 r180 top value=200pF
C29 "GRM188R61E475KE15D" FP-GRM188R61E475KE15D_0603-MFG 20.597,26.452 r90 top value=4.7µF
C30 "GCM188R71E104KA57D" 0603 22.862,26.218 r90 top value=0.1uF
C31 "06035A560FAT2A" 0603 17.502,27.741 r180 top value=56pF
C32 "06035A560FAT2A" 0603 18.519,14.59 r180 top value=56pF
C33 "06035A560FAT2A" 0603 18.495,16.532 r180 top value=56pF
C34 "06035A560FAT2A" 0603 18.045,29.683 r180 top value=56pF
C35 "GMC31X7R106K50NT" FP-GMC31X7R106K50NT_1206-MFG 47.732,28.616 r180 bottom value=10µF
C36 "C0805C104K5RAC7800" FP-C0805C104K5RAC7800_0805-MFG 39.123,31.481 r180 top value=100nF
C37 "CL10B105KB9VPJC" FP-CL10B105KB9VPJC_0603-MFG 40.762,29.541 r90 bottom value=1µF
C38 "C1206C106J4RACAUTO" FP-C1206C106J4RACAUTO_1206-MFG 47.573,26.158 r0 bottom value=10µF
C39 "C0805C104K5RAC7800" FP-C0805C104K5RAC7800_0805-MFG 39.04,26.653 r0 top value=100nF
C40 "GRM188C71C105KA12D" FP-GRM188C71C105KA12D_0603-MFG 40.762,26.833 r90 bottom value=1µF
C41 "06033C101KAT2A" 0603 39.469,29.066 r0 top value=100pF
C42 "GRM188R61E475KE15D" FP-GRM188R61E475KE15D_0603-MFG 20.697,12.051 r90 top value=4.7µF
C43 "GCM188R71E104KA57D" 0603 22.962,12.259 r90 top value=0.1uF
C44 "GRT188R61H225KE13D" 0603 38.893,20.281 r0 bottom value=2.2uF
C45 "GRT188R61H225KE13D" 0603 39.512,20.274 r180 top value=2.2uF
C46 "GRM1885C1H201JA01D" 0603 22.129,16.975 r180 top value=200pF
C47 "GRM1885C1H201JA01D" 0603 22.129,18.916 r180 top value=200pF
C48 "GMC31X7R106K50NT" FP-GMC31X7R106K50NT_1206-MFG 47.996,15.477 r180 bottom value=10µF
C49 "C0805C104K5RAC7800" FP-C0805C104K5RAC7800_0805-MFG 39.047,17.86 r180 top value=100nF
C50 "CL10B105KB9VPJC" FP-CL10B105KB9VPJC_0603-MFG 40.637,15.74 r90 bottom value=1µF
C51 "C1206C106J4RACAUTO" FP-C1206C106J4RACAUTO_1206-MFG 47.928,13.019 r0 bottom value=10µF
C52 "C0805C104K5RAC7800" FP-C0805C104K5RAC7800_0805-MFG 39.047,13.032 r0 top value=100nF
C53 "GRM188C71C105KA12D" FP-GRM188C71C105KA12D_0603-MFG 40.597,13.032 r90 bottom value=1µF
C54 "06033C101KAT2A" 0603 39.443,15.445 r0 top value=100pF
C55 "C0603C104K5RAC3121" FP-C0603C104K5RAC3121_0603-MFG 44.213,29.366 r270 bottom value=100nF
C56 "C0603C104K5RAC3121" FP-C0603C104K5RAC3121_0603-MFG 40.346,36.084 r180 top value=100nF
C57 "C0603C104K5RAC3121" FP-C0603C104K5RAC3121_0603-MFG 44.651,9.779 r90 bottom value=100nF
C58 "C0603C104K5RAC3121" FP-C0603C104K5RAC3121_0603-MFG 42.62,17.009 r180 bottom value=100nF
D1 "RB060M-40TFTR" SOD-123 41.955,38.657 r0 top value=40V
D2 "RB060M-40TFTR" SOD-123 42.604,1.819 r0 top value=40V
D3 "LH R974-LP-1" LH_R974_Red 2.427,31.996 r90 top value=Red
D4 "LH R974-LP-1" LH_R974_Red 5.135,31.996 r90 top value=Red
D5 "LH R974-LP-1" LH_R974_Red 7.843,31.996 r90 top value=Red
D6 "KG DELLS1.22-JGKH-24" "FP-KG DELLS1.22-JGKH-24_0603-MFG" 15.791,18.655 r0 top
D7 "KG DELLS1.22-JGKH-24" "FP-KG DELLS1.22-JGKH-24_0603-MFG" 15.576,31.671 r0 top
D8 "STTH112A" SMA 59,39.749 r270 bottom value=1200V
D9 "STTH112A" SMA 58.676,43.406 r270 top value=1200V
D10 "BZT52C2V7T-7" SOD-523 49.259,36.935 r0 top value=2.7V
D11 "MMSZ4701-HE3-08" SOD-123 45.666,36.524 r180 bottom value=14V
D12 "DFLZ30-7" PowerDI123 45.072,39.293 r180 bottom value=30V
D13 "STTH112A" SMA 59.238,7.707 r90 bottom value=1200V
D14 "STTH112A" SMA 59.238,4.067 r90 top value=1200V
D15 "BZT52C2V7T-7" SOD-523 49.853,8.784 r90 top value=2.7V
D16 "MMSZ4701-HE3-08" SOD-123 48.204,10.367 r180 bottom value=14V
D17 "DFLZ30-7" PowerDI123 48.019,7.598 r180 bottom value=30V
D18 "STTH112A" SMA 57.1,37.749 r180 top value=1200V
D19 "STTH112A" SMA 57.2,9.475 r180 top value=1200V
FID1 "Fiducial" Fiducial10-20#1 12.179,33.479 r90 top
FID2 "Fiducial" Fiducial10-20#2 4.811,2.39 r90 bottom
J1 "22281020" FP-22281020_HDR2-MFG 7.631,3.734 r270 top
J2 "MMCX-J-P-H-ST-TH1" Samtec_MMCX-J-P-H-ST-TH1 56.411,27.106 r0 top locked
J3 "SSW-102-01-G-D" Samtec_SSW-102-01-x-D 56.9,32.487 r0 top
J4 "22281020" FP-22281020_HDR2-MFG 53.348,48.955 r180 top locked
J5 "034-1030-12G" Amphenol_034-1030-12G 6,12.415 r0 top
J6 "MMCX-J-P-H-ST-TH1" Samtec_MMCX-J-P-H-ST-TH1 56.411,19.58 r0 top locked
J7 "SSW-102-01-G-D" Samtec_SSW-102-01-x-D 56.898,14.199 r180 top
J8 "22281020" FP-22281020_HDR2-MFG 53.348,-2.27 r0 top locked
J9 "034-1030-12G" Amphenol_034-1030-12G 6,23.194 r0 top
L1 "AIML-0603-3R3K-T" 0603 37.924,38.459 r90 top value=3.3uH
L2 "AIML-0603-3R3K-T" 0603 37.793,2.321 r90 top value=3.3uH
LBL1 "THT-14-423-10" Label_650x200 20.284,24.554 r180 bottom
Logo2 "CE Mark" CE_Mark_5mm 25.139,32.409 r180 bottom
Logo3 "FCC disclaimer" FCC_disclaimer 32.8,17.144 r270 bottom
Logo4 "WEEE logo" WEEE_Minimum 26.098,41.089 r180 bottom
LOGO5 "CAUTION HOT SURFACE" IEC_HotSurface_Medium 23.453,16.471 r180 bottom
LOGO6 "DANGER HIGH VOLTAGE" IEC_HighVoltage_Medium 23.453,5.476 r180 bottom
NT1 "Net-Tie" Net-Tie_0805_HV_NoOverlay 40.362,38.073 r270 bottom net-tie
NT2 "Net-Tie" Net-Tie_0805_HV_NoOverlay 40.925,2.899 r0 bottom net-tie
Q1 "BUK6D23-40EX" FP-BUK6D23-40EX_SOT1220-MFG 44.25,32.201 r270 top
Q2 "BUK6D43-40PX" FP-BUK6D43-40PX_SOT1220-MFG 44.228,26.783 r270 top
Q3 "BUK6D23-40EX" FP-BUK6D23-40EX_SOT1220-MFG 49.82,31.813 r0 bottom
Q4 "BUK6D23-40EX" FP-BUK6D23-40EX_SOT1220-MFG 44.089,17.601 r270 top
Q5 "BUK6D43-40PX" FP-BUK6D43-40PX_SOT1220-MFG 44.074,12.234 r270 top
Q6 "BUK6D23-40EX" FP-BUK6D23-40EX_SOT1220-MFG 49.43,20.483 r90 bottom
R1 "RT0603DRE0710KL" 0603 17.621,42.543 r180 top value=10.0k
R2 "TNPW12061R00DEEA" FP-TNPW12061R00DEEA_1206-MFG 48.96,34.443 r0 top value=1
R3 "RT0603BRD0715KL" 0603 20.466,45.186 r90 top value=15.0k
R4 "ERA-3AED513V" FP-ERA-3AED513V_0603-MFG 36.934,44.008 r180 bottom value=51k
R5 "RT0603DRE0710KL" 0603 22.794,45.11 r270 top value=10.0k
R6 "RT0603DRE072K4L" 0603 45.826,46.356 r180 top value=2.40k
R7 "RG1608P-303-B-T5" 0603 10.003,41.443 r90 top value=30.0k
R8 "RT0603DRE0710KL" 0603 17.371,6.476 r180 top value=10.0k
R9 "P2TC0603D1002LNTA" FP-P2TC0603D1002LNTA_0603-MFG 9.554,38.284 r0 top value=10k
R10 "RT0603BRD0715KL" 0603 41.286,9.505 r0 bottom value=15.0k
R11 "RT0603BRD0715KL" 0603 14.978,8.565 r180 top value=15.0k
R12 "ERA-3AED513V" FP-ERA-3AED513V_0603-MFG 35.012,10.14 r0 bottom value=51k
R13 "RT0603DRE0710KL" 0603 18.583,8.415 r0 top value=10.0k
R14 "RT0603DRE072K4L" 0603 41.219,9.505 r180 top value=2.40k
R15 "560112116005" FP-560112116005_0603-MFG 18.569,20.144 r180 top value=10k
R16 "560112116005" FP-560112116005_0603-MFG 18.354,33.204 r180 top value=10k
R17 "ERJ-3EKF1202V" 0603 10.233,30.241 r90 top value=12.0k
R18 "RT0603BRE078KL" FP-RT0603BRE078KL_0603-MFG 15.446,24.116 r0 top value=8k
R19 "RT0603BRE078KL" FP-RT0603BRE078KL_0603-MFG 15.745,10.736 r0 top value=8k
R20 "560112116140" FP-560112116140_0603-MFG 18.569,18.486 r0 top value=24.9k
R21 "560112116140" FP-560112116140_0603-MFG 18.354,31.546 r0 top value=24.9k
R22 "RT0603BRD07120RL" 0603 21.65,34.915 r0 top value=120
R23 "RT0603BRD07120RL" 0603 21.65,28.99 r0 top value=120
R24 "CRCW120632R4FKEA" 1206 43.314,33.338 r0 bottom value=32.4
R25 "560112116005" FP-560112116005_0603-MFG 44.138,29.816 r0 top value=10k
R26 "TNPW12061R00DEEA" FP-TNPW12061R00DEEA_1206-MFG 48.96,31.934 r0 top value=1
R27 "CRCW12063R30JNEA" 1206 48.815,29.127 r0 top value=3.3
R28 "RT0603DRE071KL" 0603 11.721,22.329 r90 top value=1.00k
R29 "RT0603BRD07120RL" 0603 38.649,27.516 r270 bottom value=120
R30 "CRCW12063R30JNEA" 1206 48.852,26.149 r0 top value=3.3
R31 "560112116005" FP-560112116005_0603-MFG 59.472,26.409 r90 top value=10k
R32 "RT0603BRD07120RL" 0603 38.712,31.121 r90 bottom value=120
R33 "TNPW12061R00DEEA" FP-TNPW12061R00DEEA_1206-MFG 48.344,18.409 r0 top value=1
R34 "ESR03EZPF10R0" FP-ESR03EZPF10R0_0603-MFG 46.837,32.059 r90 bottom value=10
R35 "RT0603DRE075K05L" 0603 18.333,24.967 r270 top value=5.05k
R36 "RT0603DRE075K05L" 0603 18.433,11.816 r270 top value=5.05k
R37 "560112116005" FP-560112116005_0603-MFG 44.275,35.235 r0 top value=10k
R38 "560112116005" FP-560112116005_0603-MFG 48.637,34.272 r180 bottom value=10k
R39 "560112116005" FP-560112116005_0603-MFG 52.286,39.091 r180 top value=10k
R40 "P2TC0603D1001LNTA" FP-P2TC0603D1001LNTA_0603-MFG 52.242,36.983 r0 top value=1k
R41 "RT0603BRD07120RL" 0603 22.129,20.856 r0 top value=120
R42 "RT0603BRD07120RL" 0603 22.125,15.032 r0 top value=120
R43 "CRCW120632R4FKEA" 1206 43.375,19.799 r0 bottom value=32.4
R44 "560112116005" FP-560112116005_0603-MFG 44.014,15.268 r0 top value=10k
R45 "TNPW12061R00DEEA" FP-TNPW12061R00DEEA_1206-MFG 48.295,21.018 r0 top value=1
R46 "CRCW12063R30JNEA" 1206 48.464,15.602 r0 top value=3.3
R47 "RT0603DRE071KL" 0603 11.721,11.348 r90 top value=1.00k
R48 "RT0603BRD07120RL" 0603 38.484,13.751 r270 bottom value=120
R49 "CRCW12063R30JNEA" 1206 48.472,12.624 r0 top value=3.3
R50 "560112116005" FP-560112116005_0603-MFG 59.688,18.916 r90 top value=10k
R51 "RT0603BRD07120RL" 0603 38.484,17.356 r90 bottom value=120
R53 "ESR03EZPF10R0" FP-ESR03EZPF10R0_0603-MFG 47.022,17.961 r90 bottom value=10
R54 "560112116005" FP-560112116005_0603-MFG 44.138,20.634 r180 top value=10k
R55 "560112116005" FP-560112116005_0603-MFG 46.972,20.644 r270 bottom value=10k
R56 "560112116005" FP-560112116005_0603-MFG 52.417,7.189 r180 top value=10k
R57 "P2TC0603D1001LNTA" FP-P2TC0603D1001LNTA_0603-MFG 52.307,9.304 r0 top value=1k
R58 "RT0603BRD0715KL" 0603 41.864,46.33 r0 top value=15.0k
TP2 "5011" Keystone5011 3.398,38.016 r0 top
U1 "UCC35131QDHARQ1" DHA0016A-MFG 30.75,40.074 r0 top
U2 "TPS7A2450DBVR" DBV0005A-MFG 6.763,41.593 r0 top
U3 "UCC35131QDHARQ1" DHA0016A-MFG 30.5,5.432 r0 top
U4 "PUCC218915AQDFPQ1" DFP0028A-MFG 30.4,29.416 r0 top
U5 "PUCC218915AQDFPQ1" DFP0028A-MFG 30.5,16.282 r0 top
ZZ1 "This Assembly Note is for PCB labels only" AssemblyNoteLabel 4.699,100.025 r0 top
ZZ2 "These assemblies are ESD sensitive, ESD precautions shall be observed." AssemblyNote 4.699,97.259 r0 top
ZZ3 "These assemblies must be clean and free from flux and all contaminants. Use of no clean flux is not acceptable." AssemblyNote 4.699,95.01 r0 top
ZZ4 "These assemblies must comply with workmanship standards IPC-A-610 Class 2, unless otherwise specified." AssemblyNote 4.699,92.761 r0 top

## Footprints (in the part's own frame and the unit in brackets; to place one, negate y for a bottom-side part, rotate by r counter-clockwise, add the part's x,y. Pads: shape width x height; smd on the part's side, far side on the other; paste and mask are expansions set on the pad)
0603 [mm] "0603 from SM-752 data"
  rect 1x0.95 smd: 1(-0.8,0) 2(0.8,0)
  silkscreen extent -1.52,-0.69 1.52,0.69, body extent -0.87,-0.47 0.87,0.47, height 1
1206 [mm] "1206 from SM-752 data"
  rect 1.3x1.85 smd: 1(-1.45,0) 2(1.45,0)
  silkscreen extent -2.4,-1.21 2.4,1.21, body extent -1.7,-0.9 1.7,0.9, height 1.35
Amphenol_034-1030-12G [mm] "BNC JACK, 75 Ohm, R/A, TH"
  rrect50% 1.14x1.14 hole 0.76: 1(0,0)
  round 2.55 hole 1.7: 2(-2.54,2.54) 3(2.54,2.54) 4(2.54,-2.54) 5(-2.54,-2.54)
  silkscreen extent -3.75,-3.75 3.75,3.75, body extent -16.55,-3.75 3.75,3.75, height 8
AssemblyNote [mm] "Assembly Note"
AssemblyNoteLabel [mm] "Assembly Note for PCB Labels"
CE_Mark_5mm [mm] "Minimum text height for CE Mark"
  silkscreen extent -3.5,-2.5 3.5,2.5
DBV0005A-MFG [mm]
  rrect17% 1.1x0.6 smd paste+0 mask+0: 1(-1.3,0.95) 2(-1.3,0) 3(-1.3,-0.95) 4(1.3,-0.95) 5(1.3,0.95)
  silkscreen extent -2.57,-1.53 0.87,1.53, body extent -1.95,-1.78 1.95,1.78, height 0.25
DFP0028A-MFG [mm] "Recommended Land Pattern"
  rrect33% 1.3x0.3 smd paste+0 mask+0: 1(-4.8,3.25) 2(-4.8,2.75) 3(-4.8,2.25) 4(-4.8,1.75) 5(-4.8,1.25) 6(-4.8,0.75) 7(-4.8,0.25) 8(-4.8,-0.25) 9(-4.8,-0.75) 10(-4.8,-1.25) 11(-4.8,-1.75) 12(-4.8,-2.25) 13(-4.8,-2.75) 14(-4.8,-3.25) 15(4.8,-3.25) 16(4.8,-2.75) 17(4.8,-2.25) 18(4.8,-1.75) 19(4.8,-1.25) 20(4.8,-0.75) 21(4.8,-0.25) 22(4.8,0.25) 23(4.8,0.75) 24(4.8,1.25) 25(4.8,1.75) 26(4.8,2.25) 27(4.8,2.75) 28(4.8,3.25)
  silkscreen extent -6.12,-3.85 3.8,3.85, body extent -5.15,-3.8 5.15,3.8, height 2.6
DHA0016A-MFG [mm] "Recommended Land Pattern"
  rrect24% 1.65x0.41 smd paste+0 mask+0: 1(-4.925,2.275) 2(-4.925,1.625) 3(-4.925,0.975) 4(-4.925,0.325) 5(-4.925,-0.325) 6(-4.925,-0.975) 7(-4.925,-1.625) 8(-4.925,-2.275) 9(4.925,-2.275) 10(4.925,-1.625) 11(4.925,-0.975) 12(4.925,-0.325) 13(4.925,0.325) 14(4.925,0.975) 15(4.925,1.625) 16(4.925,2.275)
  silkscreen extent -6.42,-2.98 3.5,2.98, body extent -5.15,-2.93 5.15,2.93, height 2.6
FCC_disclaimer [mm]
Fiducial10-20#1 [mm]
  round 1 smd mask+0.5: 33(0,0)
  Top Layer keep-out circle w1.178: c0,0 r0.5
Fiducial10-20#2 [mm]
  round 1 smd mask+0.5: 1(0,0)
  Top Layer keep-out circle w1.178: c0,0 r0.5
FP-22281020_HDR2-MFG [mm]
  rrect6% 1.57x1.57 hole 1.02 paste-1000 mask+0: 1(1.27,4.84)
  round 1.57 hole 1.02 paste-1000 mask+0: 2(-1.27,4.84)
  silkscreen extent -2.67,-4.41 2.67,6.33, body extent -2.77,-5.58 2.77,5.72, height 0.25
FP-560112116005_0603-MFG [mm] "Recommended Land Pattern"
  rrect17% 0.6x0.9 smd paste+0 mask+0: 1(-0.75,0) 2(0.75,0)
  silkscreen extent -0.08,-0.45 0.08,0.45, body extent -0.8,-0.4 0.8,0.4, height 0.6
FP-560112116140_0603-MFG [mm] "Recommended Land Pattern"
  rrect17% 0.6x0.9 smd paste+0 mask+0: 1(-0.75,0) 2(0.75,0)
  silkscreen extent -0.08,-0.45 0.08,0.45, body extent -0.8,-0.4 0.8,0.4, height 0.6
FP-BUK6D23-40EX_SOT1220-MFG [mm]
  rrect29% 0.43x0.35 smd paste-1000 mask+0: 1(-0.935,0.65) 2(-0.935,0) 3(-0.935,-0.65) 4(0.935,-0.65) 5(0.935,0) 6(0.935,0.65)
  rrect9% 1.1x1.25 smd paste-1000 mask+0: 7(0,0.285)
  rrect29% 0.66x0.35 smd paste-1000 mask+0: 8(0,-0.775)
  silkscreen extent -1.82,-1.3 1.05,1.3, body extent -1.25,-1.15 1.25,1.15, height 0.25
FP-BUK6D43-40PX_SOT1220-MFG [mm]
  rrect29% 0.43x0.35 smd paste-1000 mask+0: 1(-0.935,0.65) 2(-0.935,0) 3(-0.935,-0.65) 4(0.935,-0.65) 5(0.935,0) 6(0.935,0.65)
  rrect9% 1.1x1.25 smd paste-1000 mask+0: 7(0,0.285)
  rrect29% 0.66x0.35 smd paste-1000 mask+0: 8(0,-0.775)
  silkscreen extent -1.82,-1.3 1.05,1.3, body extent -1.25,-1.15 1.25,1.15, height 0.25
FP-C0603C104K5RAC3121_0603-MFG [mm]
  rrect13% 0.75x0.9 smd paste+0 mask+0: 1(-0.6,0) 2(0.6,0)
  silkscreen extent -0.89,-0.82 0.87,0.82, body extent -0.8,-0.4 0.8,0.4, height 0.87
FP-C0603X471F5GACTU_0603-MFG [mm]
  rrect12% 0.85x0.9 smd paste+0 mask+0: 1(-0.65,0) 2(0.65,0)
  silkscreen extent -0.88,-0.82 0.88,0.82, body extent -1.2,-0.6 1.2,0.6, height 0.25
FP-C0805C104K5RAC7800_0805-MFG [mm]
  rrect11% 0.95x1.35 smd paste+0 mask+0: 1(-0.75,0) 2(0.75,0)
  silkscreen extent -1.1,-1.05 1.1,1.05, body extent -1,-0.63 1,0.63, height 0.88
FP-C1206C105J5RECAUTO_1206-MFG [mm]
  rrect11% 0.95x1.7 smd paste+0 mask+0: 1(-1.4,0) 2(1.4,0)
  silkscreen extent -0.55,-0.9 0.55,0.9, body extent -1.97,-1 1.97,1, height 0.25
FP-C1206C106J4RACAUTO_1206-MFG [mm]
  rrect11% 0.95x1.7 smd paste+0 mask+0: 1(-1.4,0) 2(1.4,0)
  silkscreen extent -0.55,-0.9 0.55,0.9, body extent -1.6,-0.8 1.6,0.8, height 1.8
FP-CGA5L2X7R1E225K160AA_1206-MFG [mm]
  rrect9% 1.1x1.35 smd paste+0 mask+0: 1(-1.65,0) 2(1.65,0)
  silkscreen extent -0.72,-0.95 0.72,0.95, body extent -2.3,-1.05 2.3,1.05, height 0.25
FP-CL10B105KB9VPJC_0603-MFG [mm]
  rrect12% 0.82x1.1 smd paste+0 mask+0: 1(-0.79,0) 2(0.79,0)
  silkscreen extent 0,-0.5 0,0.5, body extent -0.8,-0.4 0.8,0.4, height 1
FP-ERA-3AED513V_0603-MFG [mm]
  rrect15% 0.65x0.9 smd paste+0 mask+0: 1(-0.725,0) 2(0.725,0)
  silkscreen extent 0,-0.5 0,0.5, body extent -0.8,-0.4 0.8,0.4, height 0.55
FP-ESR03EZPF10R0_0603-MFG [mm]
  rrect20% 0.5x0.8 smd paste+0 mask+0: 1(-0.75,0) 2(0.75,0)
  silkscreen extent -0.13,-0.45 0.13,0.45, body extent -0.8,-0.4 0.8,0.4, height 0.55
FP-GMC31X7R106K50NT_1206-MFG [mil]
  rrect10% 40x65 smd paste+0 mask+0: 1(-60,0) 2(60,0)
  silkscreen extent -25,-35 25,35, body extent -84,-39 84,39, height 10
FP-GRM188C71C105KA12D_0603-MFG [mm]
  rrect15% 0.65x0.7 smd paste+0 mask+0: 1(-0.675,0) 2(0.675,0)
  silkscreen extent -0.85,-0.75 0.85,0.75, body extent -0.8,-0.4 0.8,0.4, height 0.9
FP-GRM188R61E475KE15D_0603-MFG [mm]
  rrect13% 0.75x0.9 smd paste+0 mask+0: 1(-0.775,0) 2(0.775,0)
  silkscreen extent -0.9,-0.9 0.9,0.9, body extent -1.25,-0.6 1.25,0.6, height 0.25
FP-GRT188C71E225KE13D_0603-MFG [mm] "Recommended Land Pattern"
  rrect13% 0.75x0.9 smd paste+0 mask+0: 1(-0.775,0) 2(0.775,0)
  silkscreen extent -0.03,-0.5 0.03,0.5, body extent -0.8,-0.4 0.8,0.4, height 1
"FP-KG DELLS1.22-JGKH-24_0603-MFG" [mm]
  rrect20% 1.05x0.5 smd paste-1000 mask+0: 1(-0.47,0)
  rrect20% 0.7x0.5 smd paste-1000 mask+0: 2(0.645,0)
  silkscreen extent -1.67,-0.63 0.75,0.63, body extent -1.09,-0.55 1.09,0.55, height 0.25
FP-KGM15BR71H104JT_0603-MFG [mm]
  rrect13% 0.8x0.75 smd paste+0 mask+0: 1(-0.75,0) 2(0.75,0)
  silkscreen extent -0.87,-0.75 0.87,0.75, body extent -1.25,-0.58 1.25,0.58, height 0.25
FP-KGM31HR71E106KU_1206-MFG [mm]
  rrect10% 1x1.6 smd paste+0 mask+0: 1(-1.5,0) 2(1.5,0)
  silkscreen extent -0.63,-0.95 0.63,0.95, body extent -2.1,-1.05 2.1,1.05, height 0.25
FP-P2TC0603D1001LNTA_0603-MFG [mm]
  rrect10% 1.01x0.98 smd paste+0 mask+0: 1(-0.68,0) 2(0.68,0)
  silkscreen extent -0.84,-0.96 0.84,0.95, body extent -0.76,-0.43 0.76,0.43, height 0.63
FP-P2TC0603D1002LNTA_0603-MFG [mm] "Recommended Land Pattern"
  rrect10% 1.01x0.98 smd paste+0 mask+0: 1(-0.68,0) 2(0.68,0)
  silkscreen extent -0.84,-0.96 0.84,0.95, body extent -0.76,-0.43 0.76,0.43, height 0.63
FP-RT0603BRE078KL_0603-MFG [mm]
  rrect13% 0.9x0.8 smd paste+0 mask+0: 1(-0.85,0) 2(0.85,0)
  silkscreen extent -0.85,-0.81 0.86,0.8, body extent -1.4,-0.55 1.4,0.55, height 0.25
FP-TNPW12061R00DEEA_1206-MFG [mm] "Recommended Land Pattern"
  rrect11% 0.9x1.7 smd paste+0 mask+0: 1(-1.45,0) 2(1.45,0)
  silkscreen extent -0.63,-0.87 0.63,0.87, body extent -1.6,-0.8 1.6,0.8, height 0.65
FP-VJ0603D220JLAAJ32_0603-IPC_C [mm]
  rrect12% 0.907x0.858 smd paste+0 mask+0: 1(-0.576,0) 2(0.576,0)
  silkscreen extent -1.03,-0.87 1.03,0.87, body extent -1.13,-0.58 1.13,0.58, height 0.25
IEC_HighVoltage_Medium [mm]
  silkscreen extent -5.51,-4.46 5.51,5.09
IEC_HotSurface_Medium [mm]
  silkscreen extent -5.51,-4.76 5.51,4.78
Keystone5011 [mil] "Keystone Multipurpose loops"
  round 87 hole 63: 1(0,0)
  silkscreen extent -70,-70 70,70, body extent -63,-63 63,62, height 319
Label_650x200 [mil] "Thermal Transfer Label"
  round 1 on Mech14: 0(0,0)
  silkscreen extent -325,-100 325,100, body extent -325,-100 325,100, height 1
LH_R974_Red [mm] "SMD, 2-Leads, Body 1.2x2mm"
  rect 1.2x1.2 smd: 1(-1.05,0) 2(1.05,0)
  silkscreen extent -1,-1 2.6,1, body extent -1.05,-0.68 1.05,0.68, height 0.9
Net-Tie_0805_HV_NoOverlay [mil] "0805_HV pads tied by 10mil copper trace which can be cut.  An 0805 part can be placed on pads."
  rect 50x63 smd paste-25: 1(-40,0) 2(40,0)
  Top Layer lines w10: 16,0 -16,0
  Top Layer keep-out lines w1: 22,30.91 22,-30.91 ; 14.96,30.91 -14.96,30.91 ; -22,30.91 -22,-30.91 ; 14.96,-30.91 -14.96,-30.91
PowerDI123 [mm] "Diodes Inc recommended land pattern, document number DS30628 Rev. 6-2"
  rect 2.2x1.4 smd: 1(-1.275,0)
  rect 0.9x1.4 smd: 2(1.275,0)
  silkscreen extent -3.1,-1.09 1.76,1.09, body extent -2.37,-0.96 1.53,0.97, height 1
Samtec_MMCX-J-P-H-ST-TH1 [mm] "Connector, MMCX, TH"
  round 1.2 hole 0.84: 1(0,0) 2(-1.27,1.27) 3(1.27,1.27) 4(1.27,-1.27) 5(-1.27,-1.27)
  silkscreen extent -1.75,-1.75 1.75,1.75, body extent -1.75,-1.75 1.75,1.75, height 4.35
Samtec_SSW-102-01-x-D [mm] "Receptacle, 2.54mm, 2x2, TH"
  rrect50% 1.55x1.55 hole 1.04: 1(-1.27,1.27)
  round 1.55 hole 1.04: 2(-1.27,-1.27) 3(1.27,1.27) 4(1.27,-1.27)
  silkscreen extent -3.1,-2.48 2.79,2.48, body extent -2.79,-2.48 2.79,2.48, height 8.51
SMA [mm] "Molded Diode, 2-Leads, Body 4.3x2.6mm, IPC Medium Density, based on OnSemi component dimensions and land pattern"
  rect 2x2 smd: 1(-2,0) 2(2,0)
  silkscreen extent -3.66,-1.57 2.79,1.57, body extent -2.6,-1.3 2.6,1.3, height 2.42
SOD-123 [mm] "On Semi recommended land pattern"
  rect 0.915x1.22 smd: 1(-1.637,0) 2(1.637,0)
  silkscreen extent -2.74,-1.17 2.03,1.17, body extent -1.93,-0.9 1.93,0.9, height 1.35
SOD-523 [mm] "NXP Semiconductor recommended land pattern, nominal STEP model"
  rect 0.8x0.6 smd paste-0.05: 1(-0.55,0) 2(0.55,0)
  silkscreen extent -1.65,-0.66 1.2,0.66, body extent -0.8,-0.4 0.8,0.4, height 0.72
WEEE_Minimum [mm] "WEEElie bin"
  silkscreen extent -2.42,-4.38 2.52,2.65

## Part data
C1 C14 C30 C43: library part CMP-0084679-1, "CAP, CERM, 0.1 µF, 25 V,+/- 10%, X7R, AEC-Q200 Grade 1, 0603", Cap_Case=0603, Manufacturer=MuRata, TempCo=X7R, Tolerance_%=10%, Value2=25V, ValueDisplayed=0.1µF
C2 C15: library part CMP-0044202-1, "10 µF ±10% 25V Ceramic Capacitor X7R 1206 (3216 Metric)", Digikey Part Number=478-KGM31HR71E106KUCT-ND, Manufacturer="KYOCERA AVX", Mouser Part Number=581-KGM31HR71E106KU, Operating Temperature Range="-55°C to +125°C", TempCo=15%, Temperature Characteristic=X7R, Tolerance_%=10%, ValueDisplayed=10uF
C3 C4 C16 C17 C35 C48: library part CMP-0093201-1, "10 µF ±10% 50V Ceramic Capacitor X7R 1206 (3216 Metric)", Manufacturer="Cal-Chip Electronics", Operating Temperature Range="-55°C to +125°C", TempCo=15%, Temperature Characteristic=X7R, Tolerance_%=10%, ValueDisplayed=10uF
C5 C18: library part CMP-0094524-1, "1 µF ±5% 50V Ceramic Capacitor X7R 1206 (3216 Metric)", Digikey Part Number=399-C1206C105J5RECAUTOCT-ND, Manufacturer=KEMET, Mouser Part Number=80-C1206C105J5RECAUT, Operating Temperature Range="-55°C to +125°C", TempCo=15%, Temperature Characteristic=X7R, Tolerance_%=5%, ValueDisplayed=1uF
C6 C19: library part CMP-0097612-1, "Cap Ceramic 470pF 50V C0G 1% SMD 0603 125°C Paper T/R", Digikey Part Number=399-C0603X471F5GAC7867CT-ND, Manufacturer=KEMET, Mouser Part Number=80-C0603X471F5G, Operating Temperature Range="-55°C to +125°C", TempCo=30ppm/°C, Temperature Characteristic=C0G, Tolerance_%=1%, ValueDisplayed=470pF
C7 C20: library part CMP-0039814-1, "22 pF ±5% 50V Ceramic Capacitor C0G, NP0 0603 (1608 Metric)", Digikey Part Number=720-VJ0603D220JLAAJ32CT-ND, Manufacturer=Vishay, Operating Temperature Range="-55°C to +150°C", TempCo=30ppm/°C, Temperature Characteristic=C0G, Tolerance_%=5%, ValueDisplayed=22pF
C8 C9 C21 C22: library part CMP-0120061-1, "0.1 µF ±5% 50V Ceramic Capacitor X7R 0603 (1608 Metric)", Digikey Part Number=478-KGM15BR71H104JTCT-ND, Manufacturer="KYOCERA AVX", Mouser Part Number=581-KGM15BR71H104JT, Operating Temperature Range="-55°C to +125°C", TempCo=15%, Temperature Characteristic=X7R, Tolerance_%=5%, ValueDisplayed=0.1uF
C10 C12 C23: library part CMP-0125378-1, "Multi-Layer Ceramic Capacitor 2.2uF 25V X7S ±10% 0603 Paper T/R", Manufacturer=Murata, Operating Temperature Range="-55°C to +125°C", TempCo=22%, Temperature Characteristic=X7S, Tolerance_%=10%, ValueDisplayed=2.2uF
C11 C24: library part CMP-0090741-1, "Cap Ceramic 2.2uF 25V X7R 10% Pad SMD 1206 +125°C Automotive T/R", Manufacturer=TDK, Operating Temperature Range="-55°C to +125°C", TempCo=15%, Temperature Characteristic=X7R, Tolerance_%=0.1%, ValueDisplayed=2.2uF
C13: library part CMP-0007508-5, "CAP, CERM, 1 uF, 50 V, +/- 10%, X7R, 0603", Cap_Case=0603, Manufacturer="Taiyo Yuden", Supplier Part Number 1=587-3247-1-ND, TempCo=X7R, Tolerance_%=10%, Value1=Unknown, Value2=50V, ValueDisplayed=1uF
C25 C26 C44 C45: library part CMP-0007502-5, "CAP, CERM, 2.2 uF, 50 V, +/- 10%, X5R, AEC-Q200 Grade 3, 0603", Cap_Case=0603, Manufacturer=MuRata, Supplier Part Number 1=490-12332-1-ND, TempCo=X5R, Tolerance_%=10%, Value1=Unknown, Value2=50V, ValueDisplayed=2.2uF
C27 C28 C46 C47: library part CMP-0007194-4, "CAP, CERM, 200 pF, 50 V, +/- 5%, C0G/NP0, 0603", Cap_Case=0603, Manufacturer=MuRata, Supplier Part Number 1=490-1434-1-ND, TempCo=C0G/NP0, Tolerance_%=5%, Value1=Unknown, Value2=50V, ValueDisplayed=200pF
C29 C42: library part CMP-0091702-1, "4.7µF ±10% 25V Ceramic Capacitor X5R 0603 (1608 Metric)", Digikey Part Number=490-14462-1-ND, Manufacturer=Murata, Mouser Part Number=81-GRM188R61E475KE5D, Operating Temperature Range="-55°C to +85°C", TempCo=15%, Temperature Characteristic=X5R, Tolerance_%=10%, ValueDisplayed=4.7uF
C31 C32 C33 C34: library part CMP-0006792-4, "CAP, CERM, 56 pF, 50 V, +/- 1%, C0G/NP0, 0603", Cap_Case=0603, Manufacturer=AVX, Supplier Part Number 1=478-7922-1-ND, TempCo=C0G/NP0, Tolerance_%=1%, Value1=Unknown, Value2=50V, ValueDisplayed=56pF
C36 C39 C49 C52: library part CMP-0120154-1, "0.1 µF ±10% 50V Ceramic Capacitor X7R 0805 (2012 Metric)", Digikey Part Number=399-C0805C104K5RAC7800CT-ND, Manufacturer=KEMET, Mouser Part Number=80-C0805C104K5R7800, Operating Temperature Range="-55°C to +125°C", TempCo=15%, Temperature Characteristic=X7R, Tolerance_%=10%, ValueDisplayed=0.1uF
C37 C50: library part CMP-0122257-1, "1 µF ±10% 50V Ceramic Capacitor X7R 0603 (1608 Metric)", Digikey Part Number=1276-CL10B105KB9VPJCCT-ND, Manufacturer=Samsung, Mouser Part Number=187-CL10B105KB9VPJC, Operating Temperature Range="-55°C to +125°C", TempCo=15%, Temperature Characteristic=X7R, Tolerance_%=10%, ValueDisplayed=1uF
C38 C51: library part CMP-0094514-1, "10 µF ±5% 16V Ceramic Capacitor X7R 1206 (3216 Metric)", Digikey Part Number=399-C1206C106J4RACAUTOCT-ND, Manufacturer=KEMET, Mouser Part Number=80-C1206C106J4RAUTO, Operating Temperature Range="-55°C to +125°C", TempCo=15%, Temperature Characteristic=X7R, Tolerance_%=5%, ValueDisplayed=10uF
